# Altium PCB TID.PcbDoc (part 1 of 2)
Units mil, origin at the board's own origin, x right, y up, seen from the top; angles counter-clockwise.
Board outline 3536 x 3093.63 mil, 4 copper layers (Top Layer, Ground plane, Supply plane, Bottom Layer), stack 79.834 mil thick; 234 components, 122 nets, 591 pads, 178 vias.
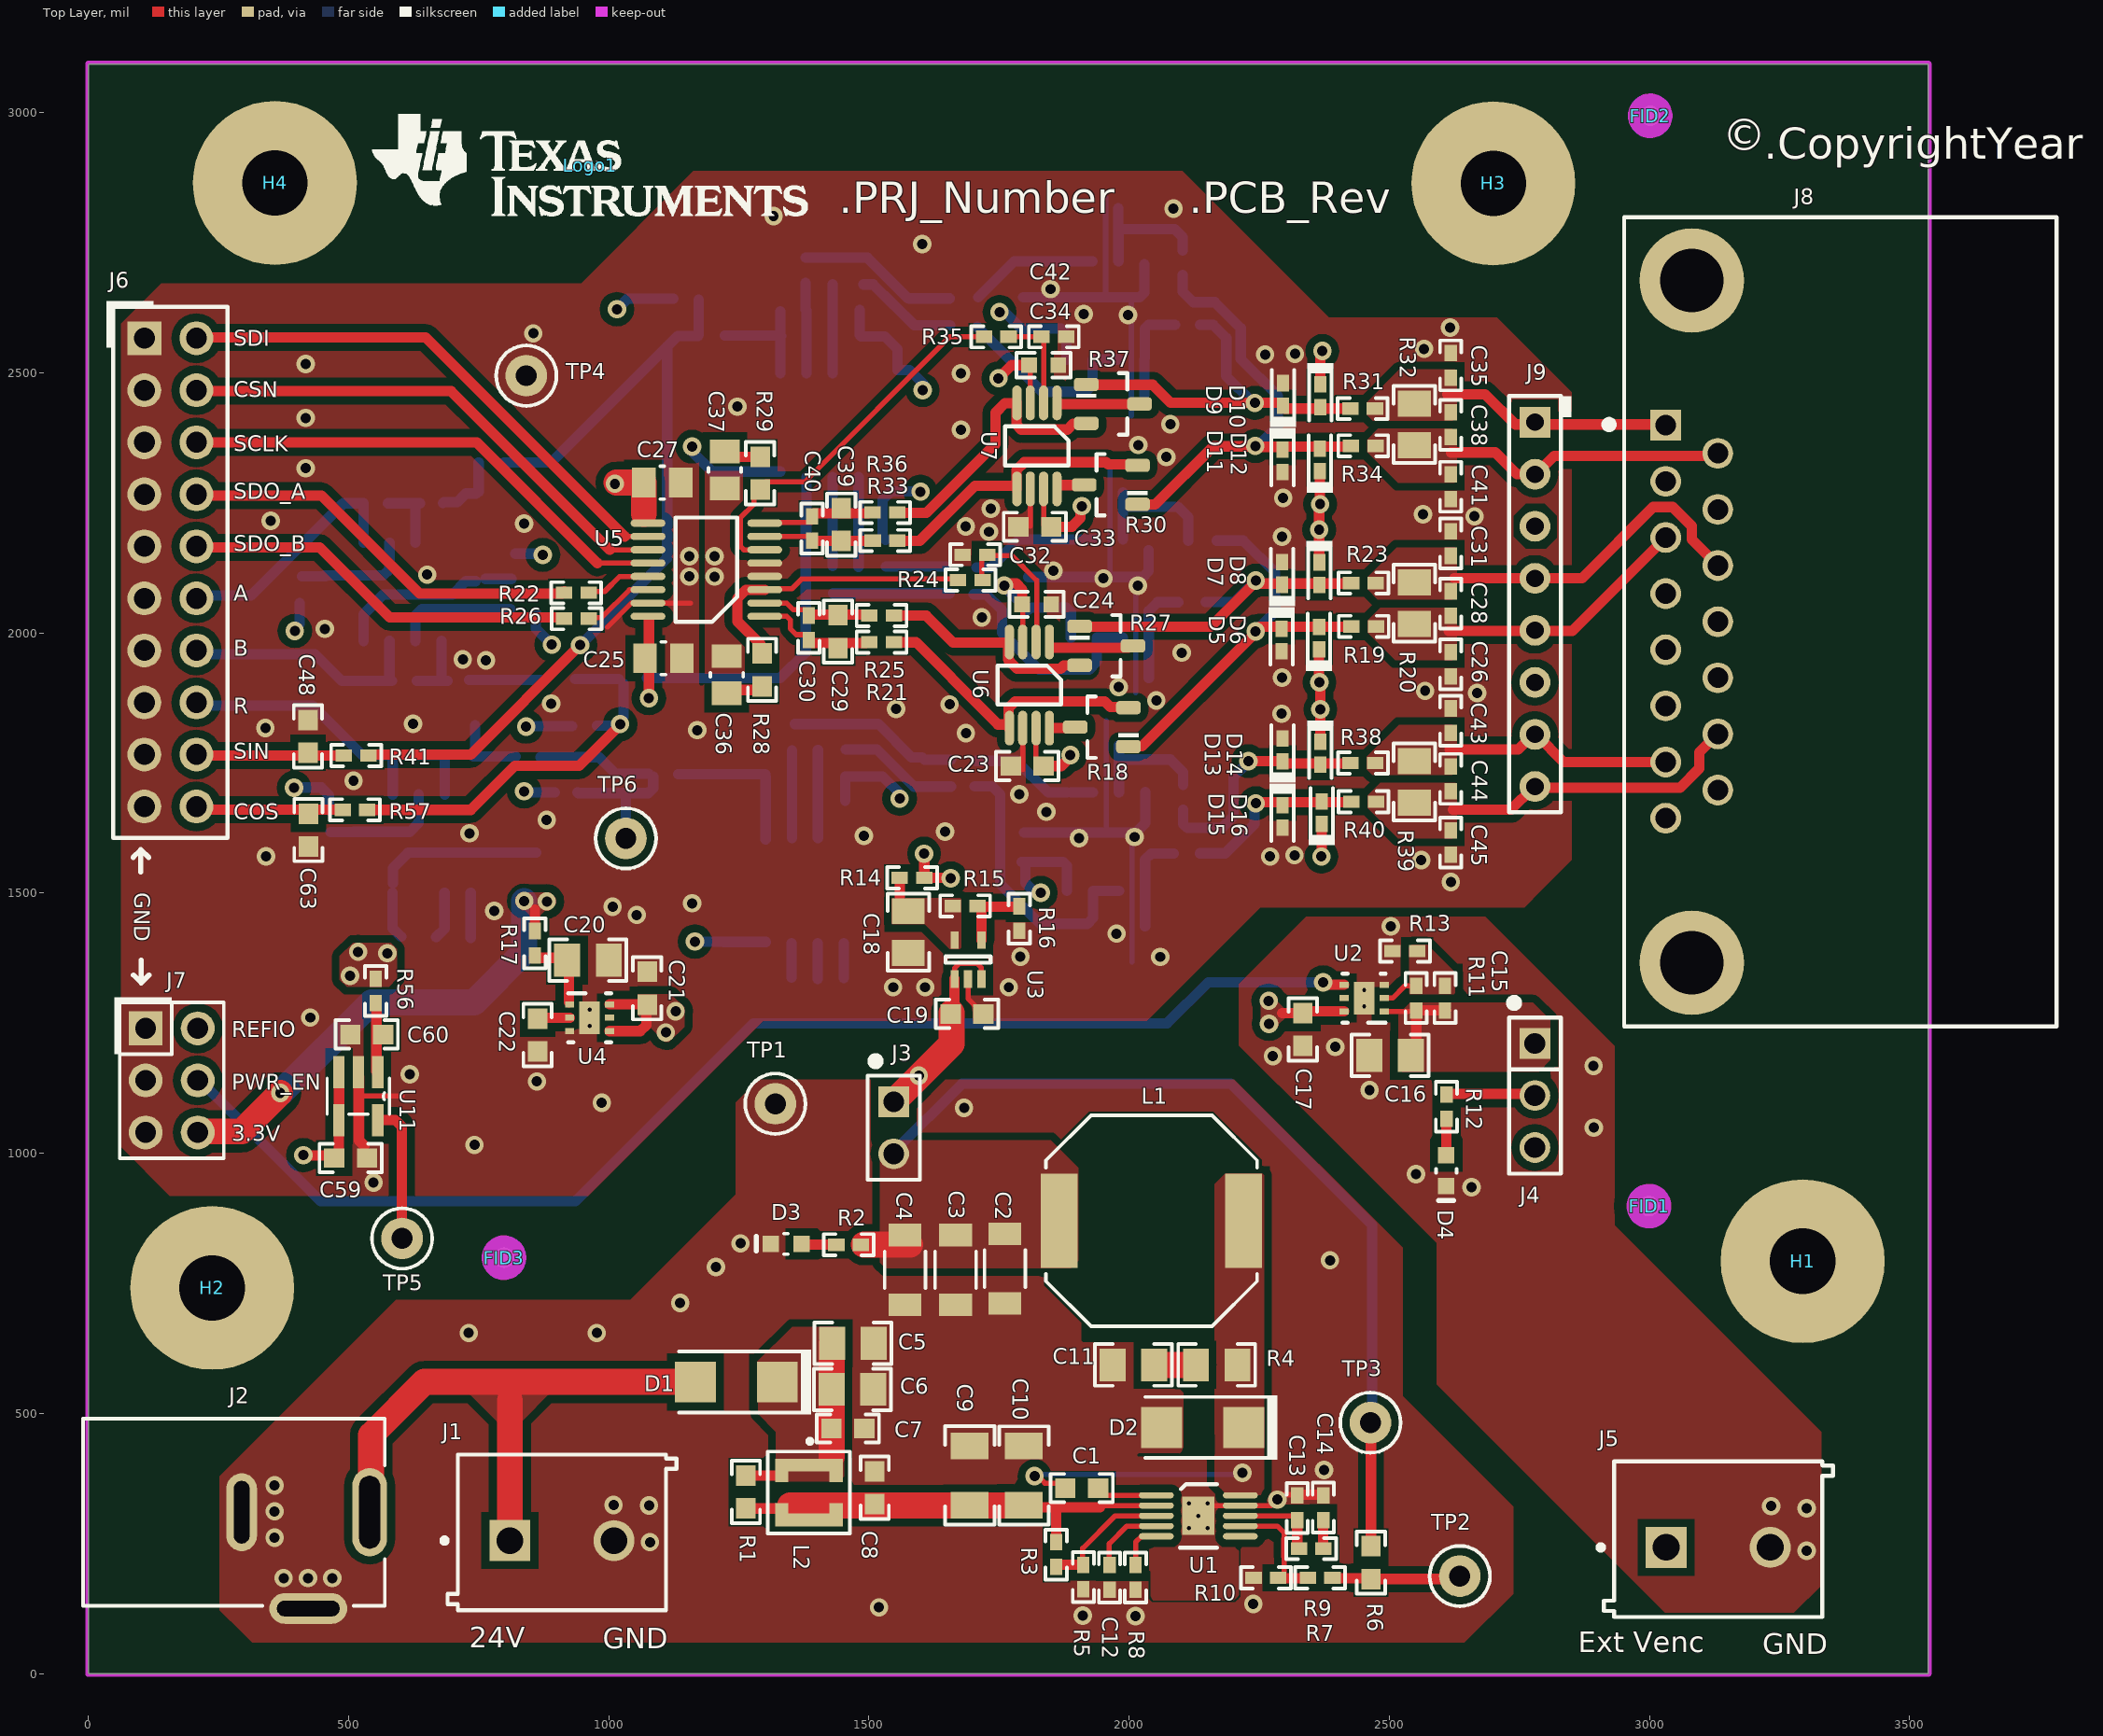
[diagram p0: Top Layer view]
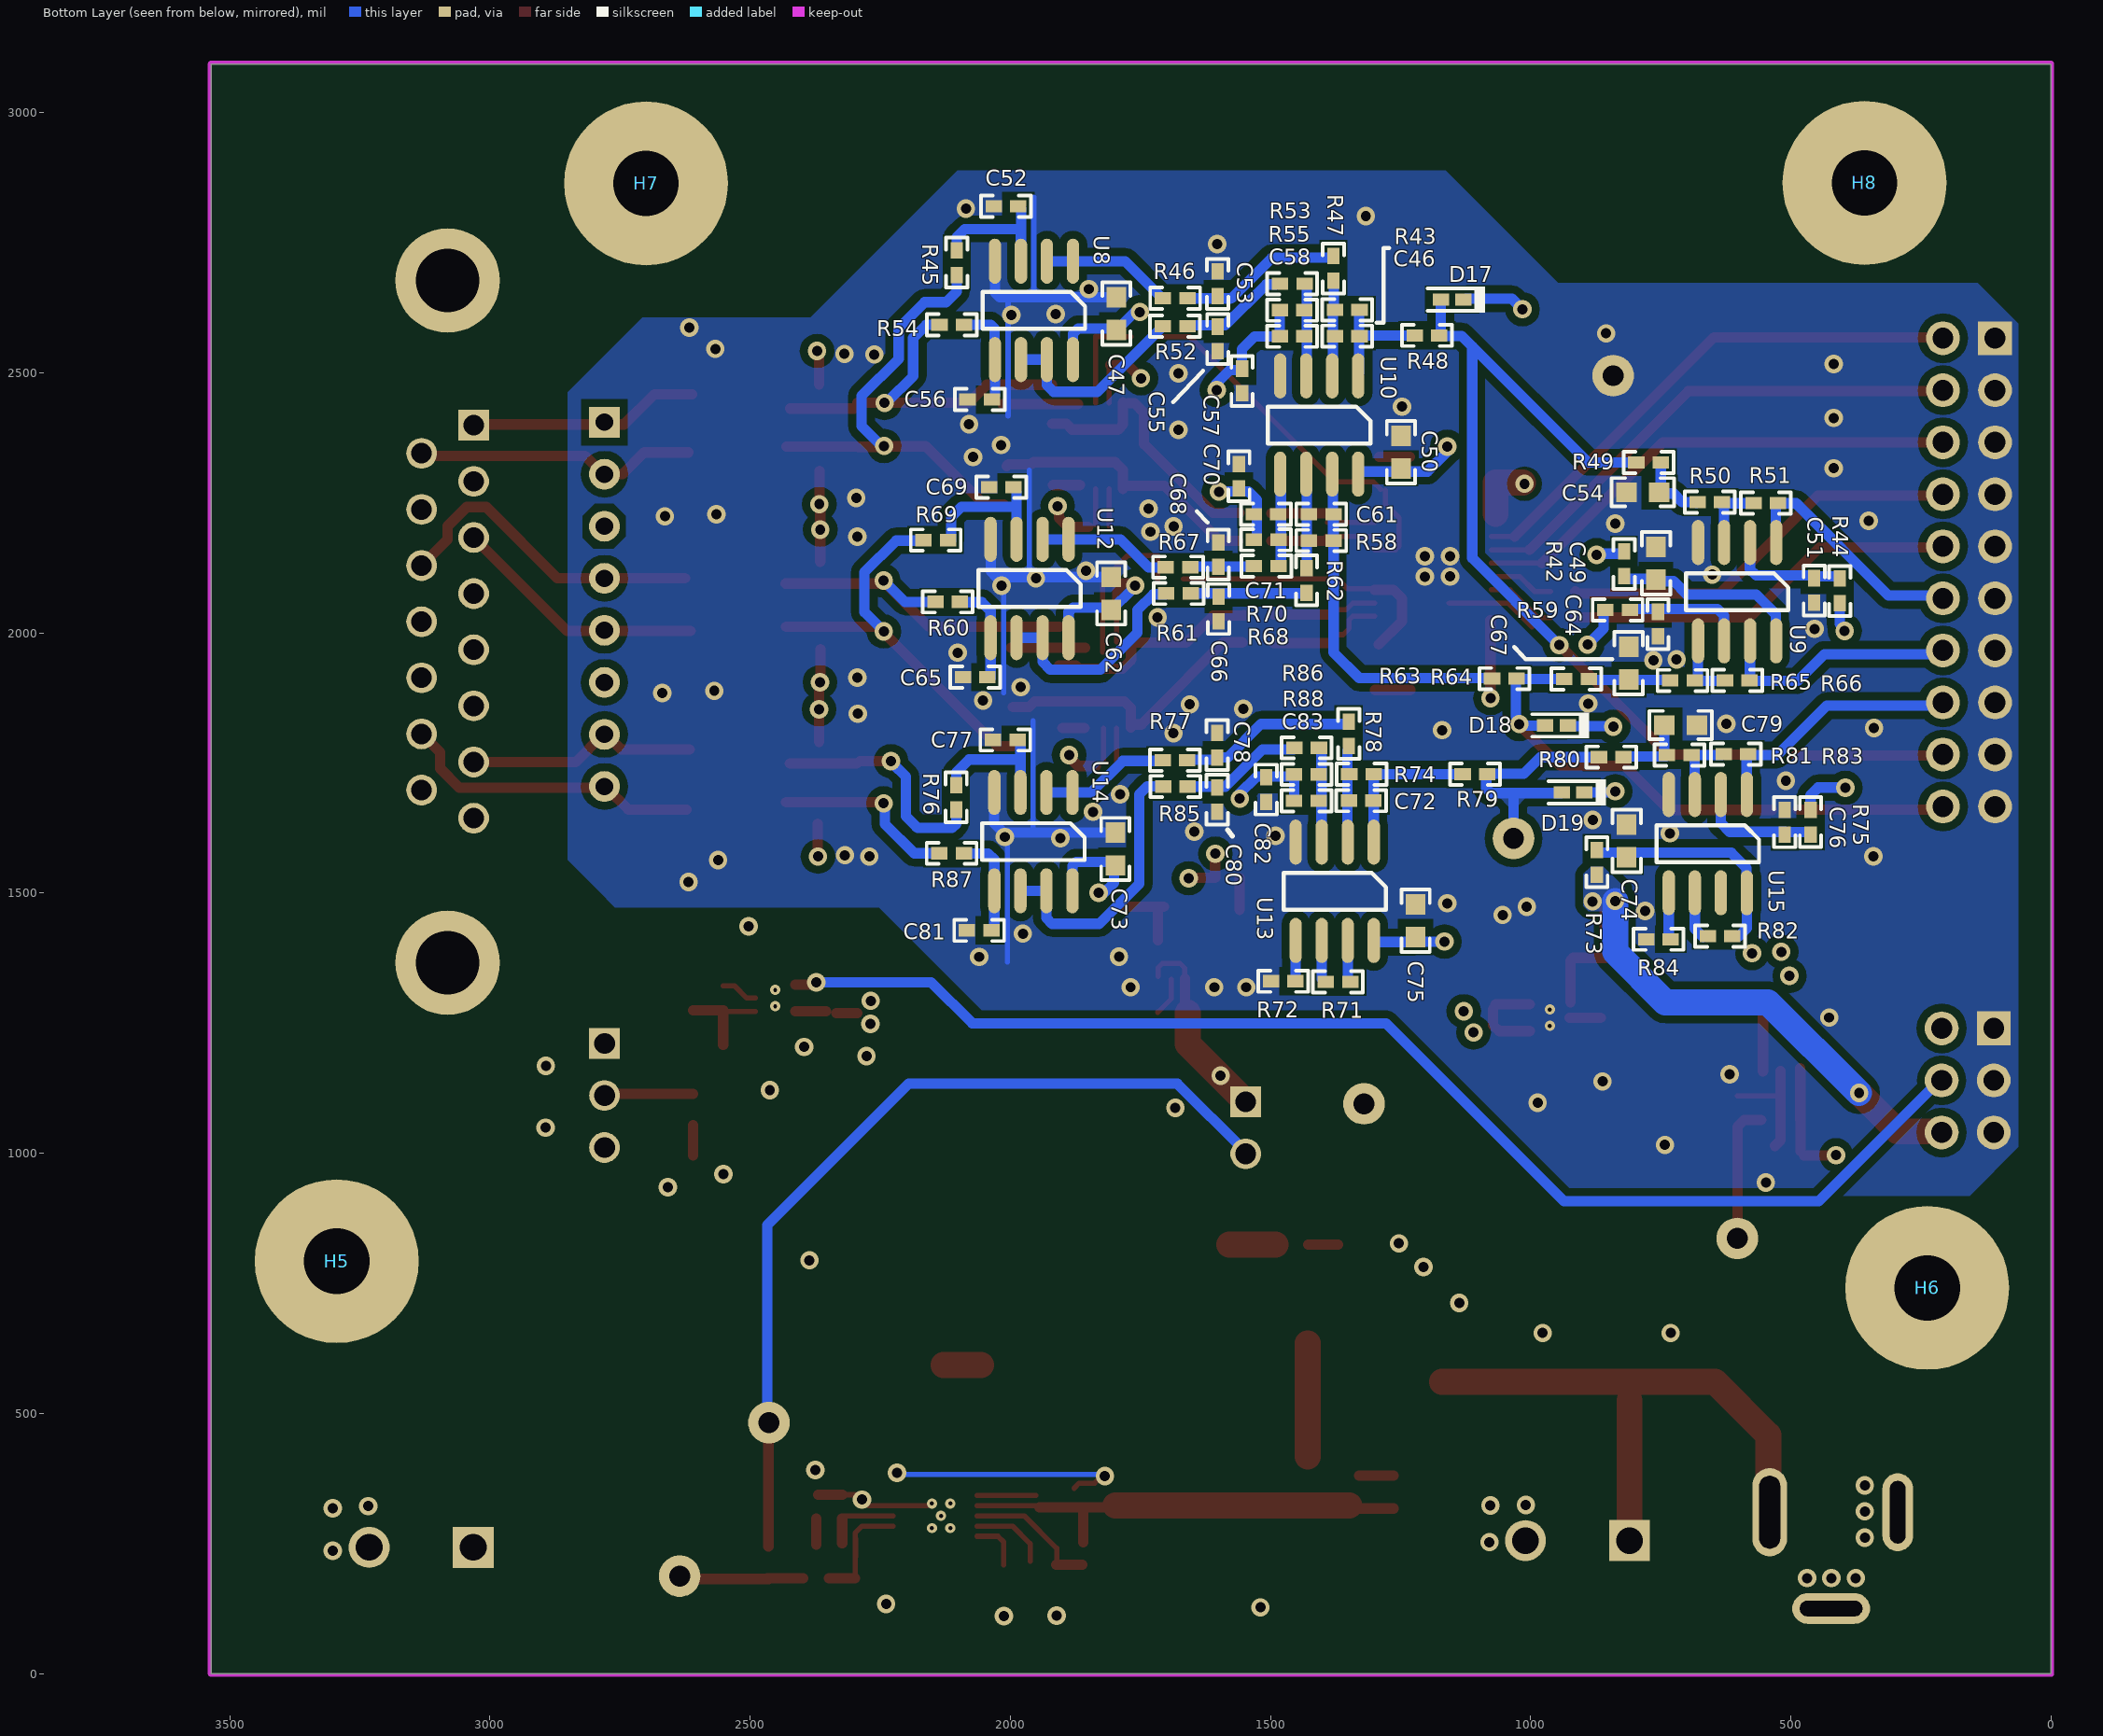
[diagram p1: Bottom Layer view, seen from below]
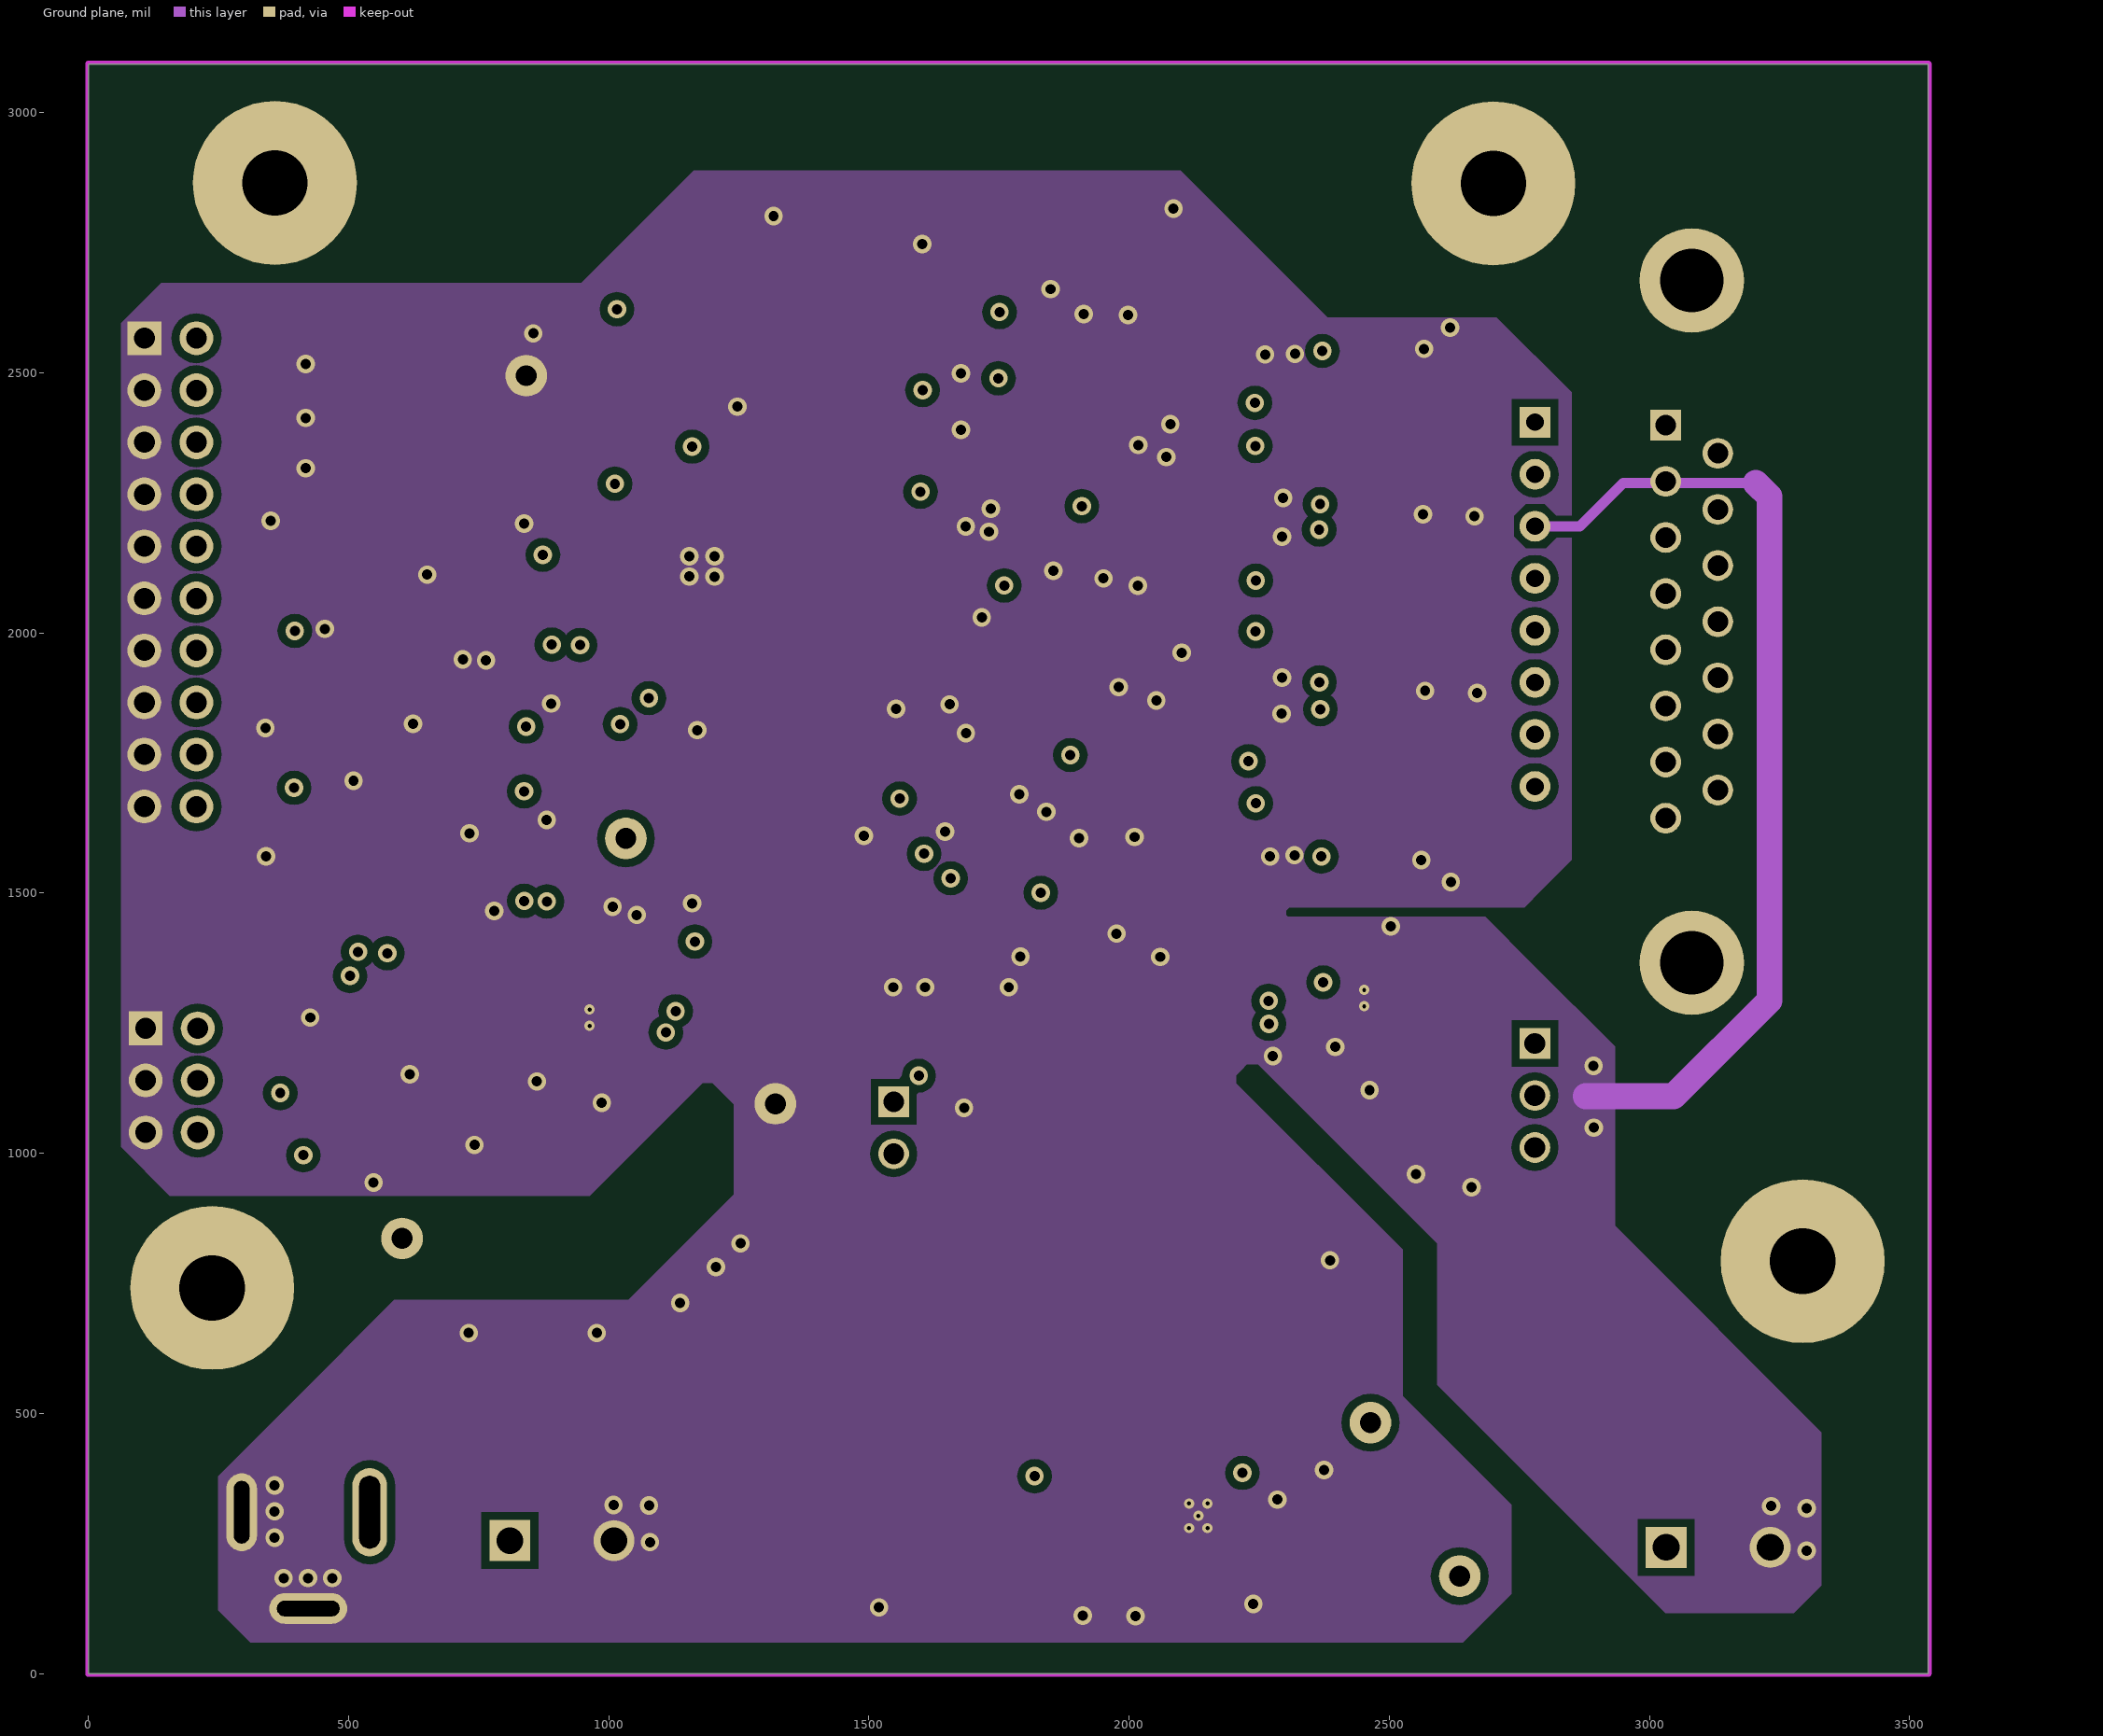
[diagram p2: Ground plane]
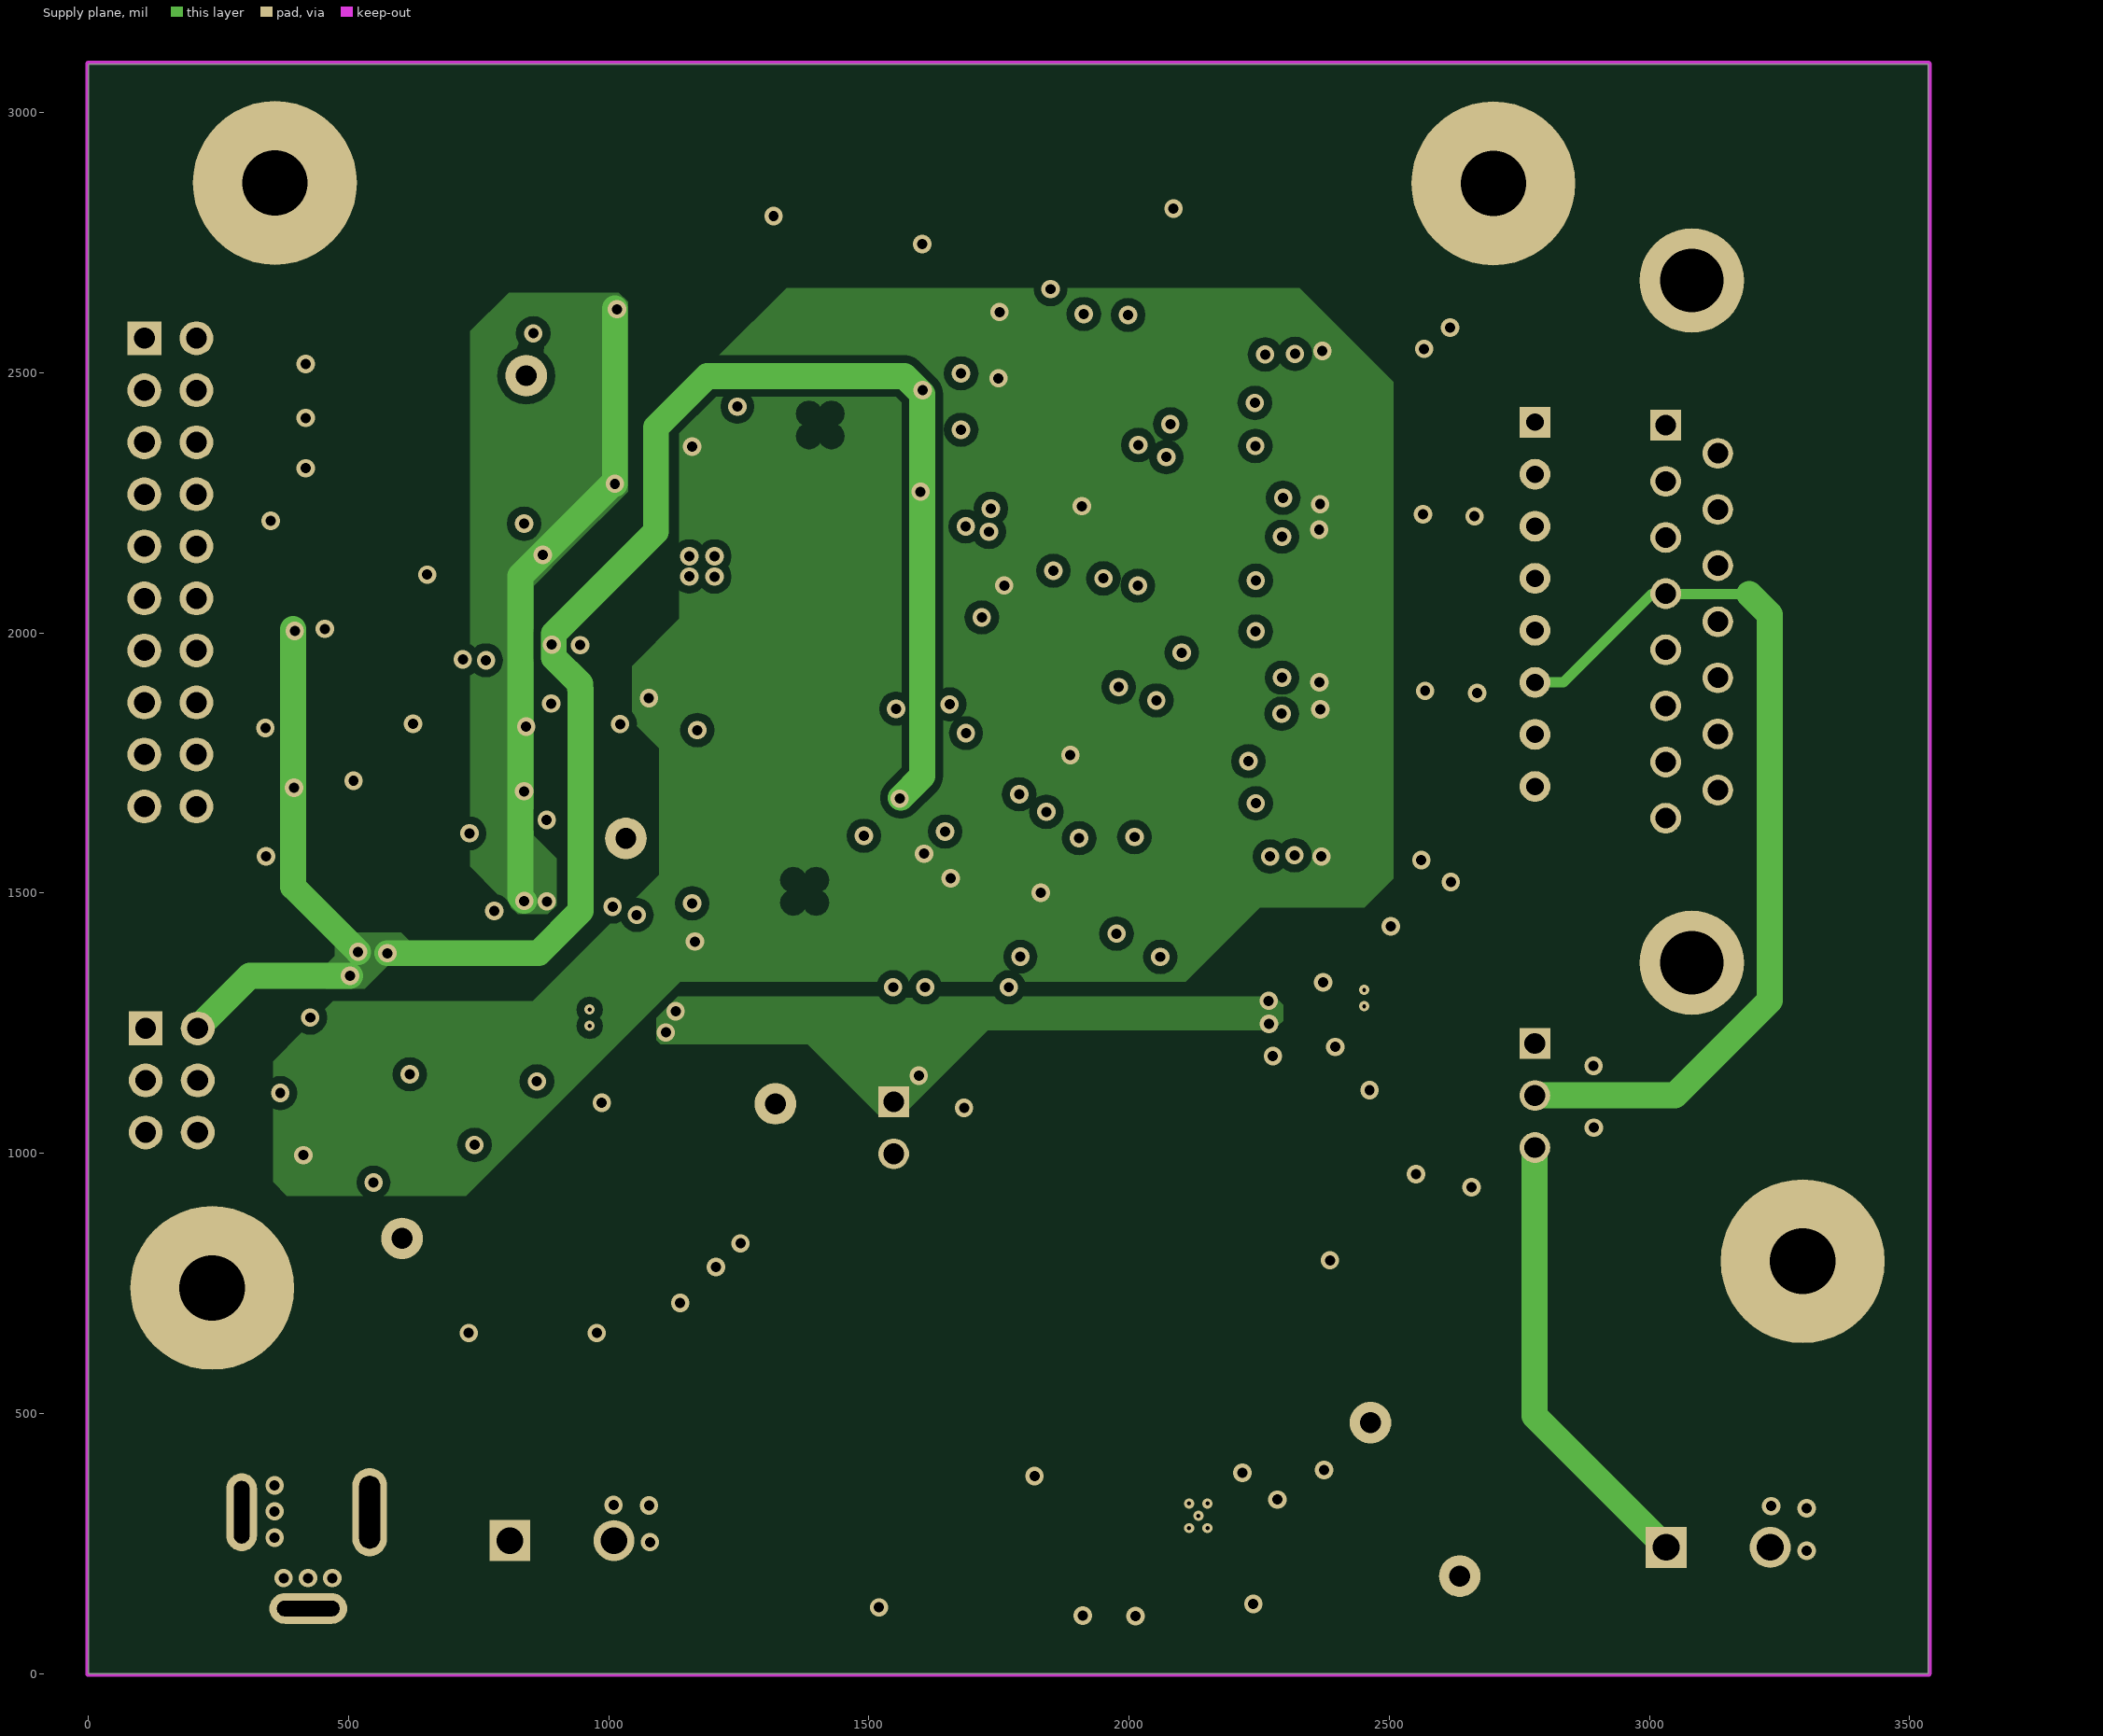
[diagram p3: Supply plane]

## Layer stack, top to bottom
Top Solder: solder mask 0.4, Solder Resist, Dk 3.5
Top Layer: signal copper 1.4
Dielectric1: core 59.2, FR-4, Dk 4.8
Ground plane: signal copper 1.417
Dielectric 3: prepreg 5, Dk 4.2
Supply plane: signal copper 1.417
Dielectric 2: core 10, Dk 4.2
Bottom Layer: signal copper 1.4
Bottom Solder: solder mask 0.4, Solder Resist, Dk 3.5

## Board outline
0,0 0,3093.63 3536,3093.63 3536,0

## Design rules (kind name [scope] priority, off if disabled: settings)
AcuteAngle [All] p1: minimum=4.50000000000000E+0001 checktracksonly=FALSE
AssemblyTestPointUsage [All] p1: valid=2
Clearance Clearance_Keepouts [((IsTrack Or IsArc) And Not InPoly) And IsFree and IsKeepOut vs ((IsTrack Or IsArc) And Not InPoly) And IsFree and IsKeepOut] p1: gap=0
Clearance Clearance_BoardEdge_MountingHoles [OnCopper and InComponentClass('Mounting Holes') vs IsKeepOut] p2: gap=40
Clearance Clearance_BoardEdge_Poly [OnCopper and InPoly vs IsKeepOut] p3: gap=25
Clearance Clearance_BoardEdge [OnCopper and Not InComponentClass('Logo') and not InComponentClass('FiducialMark') and not InRegion(1000,500,4000,800) and Not IsKeepout vs IsKeepOut] p4: gap=75
Clearance Clearance_Poly [InPolygon] p5: gap=15
Clearance [All] p6: gap=7.87
ComponentClearance ComponentClearance_MountingHoles_FiducialMarks [InComponentClass('Mounting Holes') vs InComponentClass('FiducialMark')] p1: gap=50 collisioncheckmode=3 verticalgap=10 showdistances=FALSE
ComponentClearance ComponentClearance_Shunt [InComponentClass('Header') vs InComponentClass('Shunt')] p2: gap=0 collisioncheckmode=3 verticalgap=0 showdistances=FALSE
ComponentClearance ComponentClearance_Logo [InComponentClass('Logo')] p3: gap=50 collisioncheckmode=3 verticalgap=10 showdistances=FALSE
ComponentClearance ComponentClearance_ScrewToNut [(HasFootprint('NY PMS 440 0025 PH')) vs (HasFootprint('Keystone_1902C'))] p4: gap=5 collisioncheckmode=3 verticalgap=10 showdistances=FALSE
ComponentClearance ComponentClearance_MountingHoles [InComponentClass('Mounting Holes')] p5: gap=118.11 collisioncheckmode=3 verticalgap=100000 showdistances=FALSE
ComponentClearance ComponentClearance_SmallPassives [HasFootprint('0201*') or HasFootprint('0402*') or HasFootprint('0508') or HasFootprint('0603*') or HasFootprint('0612') or HasFootprint('0805*') or HasFootprint('0815*') or HasFootprint('0830*') or HasFootprint('1206*') or HasFootprint('1210*') or HasFootprint('1808*') or HasFootprint('1812*') or HasFootprint('1825*') or HasFootprint('2010*') or HasFootprint('2220*') or HasFootprint('2225*') or HasFootprint('2512*') or HasFootprint('2728*') or HasFootprint('3518*') vs HasFootprint('0201*') or HasFootprint('0402*') or HasFootprint('0508') or HasFootprint('0603*') or HasFootprint('0612') or HasFootprint('0805*') or HasFootprint('0815*') or HasFootprint('0830*') or HasFootprint('1206*') or HasFootprint('1210*') or HasFootprint('1808*') or HasFootprint('1812*') or HasFootprint('1825*') or HasFootprint('2010*') or HasFootprint('2220*') or HasFootprint('2225*') or HasFootprint('2512*') or HasFootprint('2728*') or HasFootprint('3518*')] p6: gap=20 collisioncheckmode=3 verticalgap=10 showdistances=FALSE
ComponentClearance ComponentClearance_THtoSMT [IsThruComponent vs IsSMTComponent] p7: gap=100 collisioncheckmode=3 verticalgap=30 showdistances=FALSE
ComponentClearance ComponentClearance_THtoTH [IsThruComponent vs IsThruComponent] p8: gap=118.11 collisioncheckmode=3 verticalgap=30 showdistances=FALSE
ComponentClearance [All] p9: gap=40 collisioncheckmode=3 verticalgap=10 showdistances=FALSE
DiffPairsRouting [All] p1: maxlimit=100 minlimit=10 mostfreqgap=10 toplayer_minwidth=15 toplayer_maxwidth=15 toplayer_prefwidth=15 midlayer1_minwidth=15 midlayer1_maxwidth=15 midlayer1_prefwidth=15 midlayer2_minwidth=15 midlayer2_maxwidth=15 midlayer2_prefwidth=15 bottomlayer_minwidth=15 bottomlayer_maxwidth=15 bottomlayer_prefwidth=15 maxuncoupledlength=1000
FabricationTestPointUsage TestPointUsage [All] p1: valid=2 allowmultiple=FALSE
FabricationTestpoint Testpoint [All] p1: side=3 testpointundercomponent=TRUE minsize=40 maxsize=100 preferedsize=60 minholesize=0 maxholesize=40 preferedholesize=32 testpointgrid=1 allowsidetop=TRUE allowsidebottom=TRUE usegrid=TRUE gridtolerance=0.01
FanoutControl Fanout_LCC [IsLCC] p1: bgadir=Out bgaviamode=Centered fanoutstyle=Auto fanoutdirection=Alternating viagrid=1 // Fanout_LCC (Default Rule)
FanoutControl Fanout_BGA [IsBGA] p2: bgadir=Out bgaviamode=Centered fanoutstyle=Auto fanoutdirection=Alternating viagrid=1 // Fanout_BGA (Default Rule)
FanoutControl Fanout_Default [All] p4: bgadir=Out bgaviamode=Centered fanoutstyle=Auto fanoutdirection=Alternating viagrid=1 // Fanout_Default (Default Rule)
FanoutControl Fanout_Small [(CompPinCount < 5)] p5: bgadir=Out bgaviamode=Centered fanoutstyle=Auto fanoutdirection=OutThenIn viagrid=1 // Fanout_Small (Default Rule)
HoleSize HoleSize_componentPAD [((Component =U1)or (Component =U2)or (Component =U4)or (Component =U10)or (Component =U13)) and isVia] p1: absolutevalues=TRUE maxlimit=251 minlimit=7.87 maxpercent=80.000 minpercent=20.000
HoleSize [All] p2: absolutevalues=TRUE maxlimit=251 minlimit=8 maxpercent=80.000 minpercent=20.000
MinimumAnnularRing MinimumAnnularRing_ThermalPadVias [IsVia and InAnyComponent] p1: minimumring=5.91
MinimumAnnularRing [All] p2: minimumring=7.87
MinimumSolderMaskSliver MinimumSolderMaskSliver_Logo [InComponentClass('Logo') vs InComponentClass('Logo')] p1: minsoldermaskwidth=0.7
MinimumSolderMaskSliver [All] p2: minsoldermaskwidth=3.94
PlaneConnect [All] p1: planeconnectstyle=Direct reliefexpansion=10 reliefentries=4 reliefconductorwidth=10 reliefairgap=10
PolygonConnect PolygonConnect_1 [All vs IsNamedPolygon('Top Layer-5VDC-LDO')] p1: connectstyle=Direct reliefconductorwidth=10 reliefentries=4 polygonreliefangle="90 Angle" airgapwidth=10
PolygonConnect [All] p2: connectstyle=Direct reliefconductorwidth=10 reliefentries=4 polygonreliefangle="90 Angle" airgapwidth=10
RoutingVias ThermalPadVias [IsVia and InAnyComponent] p1: holewidth=7.87 width=19.68 viastyle="Through Hole" minholewidth=7.87 minwidth=19.68 maxholewidth=12.99 maxwidth=23.62
RoutingVias [All] p2: holewidth=16 width=34 viastyle="Through Hole" minholewidth=7.87 minwidth=26 maxholewidth=40 maxwidth=65
SilkToBoardRegionClearance [Not ((IsComment or IsDesignator) And (Hide <> 'False')) and not ( InRegion(1000,500,4000,800) or InRegion(665,1651,706,2036)or InRegion(4202,2766,4505,4364))] p1:
SilkToSilkClearance SilkToSilkClearance_Pb-FreeLogo [(HasFootprint('Pb-Free_Overlay_Medium') OR HasFootprint('Pb-Free_Overlay_Small')) vs (HasFootprint('Pb-Free_Overlay_Medium') OR HasFootprint('Pb-Free_Overlay_Small'))] p1: silktosilkclearance=0
SilkToSilkClearance [All] p2: silktosilkclearance=5
SilkToSolderMaskClearance "Silk to Solder Mask Opening" [not isVia vs not isVia] p1: minsilkscreentomaskgap=1 clearancetoexposedcopper=FALSE
SolderMaskExpansion [All] p1: expansion=1.97
UnpouredPolygon [All] p1: allowunpoured=FALSE
Width [All] p1: maxlimit=100 minlimit=6 preferedwidth=10 checkconnectedcopper=TRUE
14 further rules are at their usual default settings.

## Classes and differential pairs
component class TIDA-00176_SCLS: C23 C24 C25 C26 C27 C28 C29 C30 C31 C32 C33 C34 C35 C36 C37 C38 C39 C40 C41 C42 C43 C44 C45 D5 D6 D7 D8 D9 D10 D11 D12 D13 D14 D15 D16 J6 J7 J8 J9 R18 R19 R20 R21 R22 R23 R24 R25 R26 R27 R28 R29 R30 R31 R32 R33 R34 R35 R36 R37 R38 R39 R40 TP4 U5 U6 U7
component class TIDA-00176_SCHS: C46 C47 C48 C49 C50 C51 C52 C53 C54 C55 C56 C57 C58 C59 C60 C61 C62 C63 C64 C65 C66 C67 C68 C69 C70 C71 C72 C73 C74 C75 C76 C77 C78 C79 C80 C81 C82 C83 D17 D18 D19 R41 R42 R43 R44 R45 R46 R47 R48 R49 R50 R51 R52 R53 R54 R55 R56 R57 R58 R59 R60 R61 R62 R63 R64 R65 R66 R67 R68 R69 R70 R71 R72 R73 R74 R75 R76 R77 R78 R79 R80 R81 R82 R83 R84 R85 R86 R87 R88 R89 R90 R91 R92 R93 R95 R202 TP5 TP6 U8 U9 U10 U11 U12 U13 U14 U15
component class TIDA-00176_PS: C1 C2 C3 C4 C5 C6 C7 C8 C9 C10 C11 C12 C13 C14 C15 C16 C17 C18 C19 C20 C21 C22 D1 D2 D3 D4 J1 J2 J3 J4 J5 L1 L2 R1 R2 R3 R4 R5 R6 R7 R8 R9 R10 R11 R12 R13 R14 R15 R16 R17 TP1 TP2 TP3 U1 U2 U3 U4
component class Header: J3 J4 J6 J7 J9
component class FiducialMark: FID1 FID2 FID3
component class TIDA-00176_BD: FID1 FID2 FID3 H1 H2 H3 H4 H5 H6 H7 H8 Logo1
component class Logo: Logo1
component class "Mounting Holes": H1 H2 H3 H4

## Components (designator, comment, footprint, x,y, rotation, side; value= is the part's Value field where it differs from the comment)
C1 "GRM188R71H104KA93D" 0603 1908.78,356.53 r0 top
C2 "CGA5L3X5R1H106K160AB" 1206_190 1761.34,778.38 r270 top
C3 "CGA5L3X5R1H106K160AB" 1206_190 1666.49,776.08 r270 top
C4 "CGA5L3X5R1H106K160AB" 1206_190 1569.35,776.08 r270 top
C5 "GRM21BR71H105KA12L" 0805_HV 1469.44,634.86 r0 top
C6 "GRM216R71H103KA01D" 0805_HV 1468.44,546.4 r0 top
C7 "GRM188R71H104KA93D" 0603 1459.49,471.28 r0 top
C8 "GRM188R71H104KA93D" 0603 1511.11,357.5 r90 top
C9 "GRM31CR61H225KA88L" 1206 1693.74,380.97 r90 top
C10 "GRM31CR61H225KA88L" 1206 1797.82,380.84 r90 top
C11 "C2012X5R1H475K125AB" 0805_HV 2008.32,593.43 r180 top
C12 "GRM155R61C222KA01D" 0402 1962.46,185.05 r270 top
C13 "GRM1555C1H160JA01D" 0402 2323.07,318.69 r90 top
C14 "GRM155R71C472KA01D" 0402 2373.22,319.04 r90 top
C15 "GRM1555C1H160JA01D" 0402 2607.19,1298.32 r90 top
C16 "GRM219R61C106KA73D" 0805_HV 2501.65,1188.37 r180 top
C17 "GRM188R61C225KE15D" 0603 2333.77,1238.22 r270 top
C18 "GRM219R61C106KA73D" 0805_HV 1575.84,1425.38 r270 top
C19 "GRM188R61C225KE15D" 0603 1688.72,1267.92 r0 top
C20 "GRM219R61C106KA73D" 0805_HV 960.11,1371.37 r0 top
C21 "GRM188R61C225KE15D" 0603 1073.87,1317.42 r90 top
C22 "GRM188R71C103KA01D" 0603 863.32,1227.39 r270 top
C23 "GRM188R71C104KA01D" 0603 1804.13,1744.36 r0 top
C24 "GRM188R71C104KA01D" 0603_HV 1822.31,2055.28 r180 top
C25 "CL21B106KOQNNNE" 0805_140 1105.17,1951.51 r180 top
C26 "GRM1555C1H221JA01D" 0402 2618.06,1939.81 r90 top
C27 "CL21B106KOQNNNE" 0805_140 1102.97,2289.06 r180 top
C28 "GRM1555C1H221JA01D" 0402 2618.06,2056.63 r90 top
C29 "GRM1885C1H222JA01D" 0603 1440.49,2002.7 r90 top
C30 "GRM1555C1H102JA01D" 0402 1384.28,2009.99 r90 top
C31 "GRM1555C1H221JA01D" 0402 2618.06,2172.05 r90 top
C32 "GRM155R71C104KA88D" 0402 1703.95,2150.48 r180 top
C33 "GRM188R71C104KA01D" 0603 1818.89,2204.18 r0 top
C34 "GRM188R71C104KA01D" 0603_HV 1835.74,2514.85 r180 top
C35 "GRM1555C1H221JA01D" 0402 2618.06,2514.35 r270 top
C36 "GRM21BR71A106KE51K" 0805_140 1226.92,1919.92 r270 top
C37 "GRM21BR71A106KE51K" 0805_140 1223,2313.26 r270 top
C38 "GRM1555C1H221JA01D" 0402 2618.06,2400.28 r270 top
C39 "GRM1885C1H222JA01D" 0603 1446.8,2208.24 r90 top
C40 "GRM1555C1H102JA01D" 0402 1390.8,2200.87 r90 top
C41 "GRM1555C1H221JA01D" 0402 2618.06,2281.08 r270 top
C42 "GRM155R71C104KA88D" 0402 1855.39,2569.36 r0 top
C43 "GRM1555C1H221JA01D" 0402 2618.06,1831.5 r90 top
C44 "GRM1555C1H221JA01D" 0402 2618.06,1719.66 r90 top
C45 "GRM1555C1H221JA01D" 0402 2618.06,1597.34 r90 top
C46 "GRM1555C1H4R7WA01D" 0402 1352.54,2570.53 r0 bottom
C47 "GRM188R71C104KA01D" 0603 1796.17,2613.76 r270 bottom
C48 "GRM1885C1H222JA01D" 0603 422.05,1801.47 r90 top
C49 "GRM188R71C104KA01D" 0603 759.09,2133.9 r270 bottom
C50 "GRM188R71C104KA01D" 0603 1249.23,2347.67 r270 bottom
C51 "GRM155R71C104KA88D" 0402 455.1,2081.76 r270 bottom
C52 "GRM1555C1E470JA01D" 0402 2008.28,2820.37 r0 bottom
C53 "GRM1535C1H101JDD5D" 0402 1601.45,2671.05 r90 bottom
C54 "GRM1885C1H222JA01D" 0603 784.27,2270.49 r0 bottom
C55 "GRM1535C1H101JDD5D" 0402 1601.27,2565.16 r270 bottom
C56 "GRM1555C1E470JA01D" 0402 2058.57,2448.67 r0 bottom
C57 "GRM155R71C104KA88D" 0402 1554.57,2484.43 r270 bottom
C58 "GRM1555C1H4R7WA01D" 0402 1458.43,2570.25 r180 bottom
C59 "GRM188R71C104KA01D" 0603 504.14,991.03 r180 top
C60 "GRM188R71C104KA01D" 0603 534.86,1228.52 r0 top
C61 "GRM1555C1H4R7WA01D" 0402 1402.39,2228.3 r0 bottom
C62 "GRM188R71C104KA01D" 0603 1806.08,2076.12 r270 bottom
C63 "GRM1885C1H222JA01D" 0603 422.91,1621.34 r270 top
C64 "GRM155R71C104KA88D" 0402 755.36,2017.14 r270 bottom
C65 "GRM1555C1E470JA01D" 0402 2067.41,1915.19 r0 bottom
C66 "GRM1535C1H101JDD5D" 0402 1599.67,2046.1 r270 bottom
C67 "GRM1885C1H222JA01D" 0603 811.6,1942.32 r90 bottom
C68 "GRM1535C1H101JDD5D" 0402 1600.24,2150.7 r90 bottom
C69 "GRM1555C1E470JA01D" 0402 2017.27,2280.27 r0 bottom
C70 "GRM155R71C104KA88D" 0402 1560.67,2301.27 r90 bottom
C71 "GRM1555C1H4R7WA01D" 0402 1508.68,2228.22 r180 bottom
C72 "GRM1555C1H4R7WA01D" 0402 1325.67,1677.94 r0 bottom
C73 "GRM188R71C104KA01D" 0603 1798.1,1584.84 r270 bottom
C74 "GRM188R71C104KA01D" 0603 815.61,1600.31 r270 bottom
C75 "GRM188R71C104KA01D" 0603 1221.13,1447.15 r270 bottom
C76 "GRM155R71C104KA88D" 0402 511.74,1636.38 r90 bottom
C77 "GRM1555C1E470JA01D" 0402 2009.58,1794.56 r0 bottom
C78 "GRM1535C1H101JDD5D" 0402 1602.64,1784.43 r90 bottom
C79 "GRM1885C1H222JA01D" 0603 711.96,1822.86 r180 bottom
C80 "GRM1535C1H101JDD5D" 0402 1602.64,1679.72 r270 bottom
C81 "GRM1555C1E470JA01D" 0402 2059.86,1428.6 r0 bottom
C82 "GRM155R71C104KA88D" 0402 1508.12,1699.13 r270 bottom
C83 "GRM1555C1H4R7WA01D" 0402 1431,1677.58 r180 bottom
D1 "MBRA160T3G" SMA 1245.27,560.56 r180 top
D2 "MBRA160T3G" SMA 2141.3,473.35 r180 top
D3 "LG L29K-G2J1-24-Z" "LG L29K_GREEN" 1340.68,825.88 r180 top
D4 "LG L29K-G2J1-24-Z" "LG L29K_GREEN" 2609.49,966.58 r270 top
D5 "ZHCS350TA" SOD-523 2293.05,1986.56 r270 top
D6 "ZHCS350TA" SOD-523 2365.05,1990.2 r90 top
D7 "ZHCS350TA" SOD-523 2293.85,2114.46 r90 top
D8 "ZHCS350TA" SOD-523 2365.36,2114.15 r270 top
D9 "ZHCS350TA" SOD-523 2295.68,2458.62 r90 top
D10 "ZHCS350TA" SOD-523 2367.3,2456.03 r270 top
D11 "ZHCS350TA" SOD-523 2294.81,2330.83 r270 top
D12 "ZHCS350TA" SOD-523 2366.48,2332.94 r90 top
D13 "ZHCS350TA" SOD-523 2294.9,1775.38 r90 top
D14 "ZHCS350TA" SOD-523 2367.53,1769.1 r270 top
D15 "ZHCS350TA" SOD-523 2294.9,1647.75 r270 top
D16 "ZHCS350TA" SOD-523 2369.92,1654.92 r90 top
D17 "ZHCS350TA" SOD-523 1150.87,2640.75 r0 bottom
D18 "ZHCS350TA" SOD-523 950.33,1822.35 r0 bottom
D19 "ZHCS350TA" SOD-523 918.36,1693.87 r0 bottom
FID1 "Fiducial" Fiducial10-20 2998.98,898.59 r0 top
FID2 "Fiducial" Fiducial10-20 3001.29,2994.04 r0 top
FID3 "Fiducial" Fiducial10-20 798.71,799.49 r0 top
H1 "NY PMS 440 0025 PH" "NY PMS 440 0025 PH" 3294.31,792.71 r0 top locked
H2 "NY PMS 440 0025 PH" "NY PMS 440 0025 PH" 237.98,741.35 r0 top locked
H3 "NY PMS 440 0025 PH" "NY PMS 440 0025 PH" 2700.01,2864.16 r0 top locked
H4 "NY PMS 440 0025 PH" "NY PMS 440 0025 PH" 358.53,2865.08 r0 top locked
H5 "1902C" Keystone_1902C 3294.31,792.71 r180 bottom locked
H6 "1902C" Keystone_1902C 237.98,741.35 r180 bottom locked
H7 "1902C" Keystone_1902C 2700.01,2864.16 r180 bottom locked
H8 "1902C" Keystone_1902C 358.53,2865.08 r180 bottom locked
J1 "OSTTC022162" On-Shore_OSTTC022162 910.05,271.55 r0 top
J2 "RAPC722X" CONN_RAPC722X -0.37,310.34 r180 top
J3 "PEC02SAAN" CONN_PEC02SAAN 1547.62,1049.14 r270 top
J4 "PEC03SAAN" CONN_PEC03SAAN 2779.82,1111.17 r270 top
J5 "OSTTC022162" On-Shore_OSTTC022162 3132.01,258.51 r0 top
J6 "PEC10DAAN" SULLINS_PEC10DAAN 157.63,2116.57 r0 top
J7 "PEC03DAAN" SULLINS_PEC03DAAN 160.21,1140.24 r270 top
J8 "D-Sub-15_2rows_Female" "Harting_09 66 252 6610" 3541.87,2021.8 r0 top
J9 "800-10-008-10-001000" Mill-Max_800-10-008-10-001000 2779.94,2055.18 r270 top
L1 "744065101" WE-TPC-XLH2 2043.14,870.34 r180 top
L2 "LPS3010-102MLB" LPS3010 1384.57,348.2 r270 top
Logo1 "Texas Instruments" TI_Stacked_Overlay_Small 964.16,2899.03 r0 top
R1 "CRCW060310R0JNEAHP" 0603 1263.52,349.09 r270 top
R2 "CRCW04021K00JNED" 0402 1461.04,824.33 r0 top
R3 "CRCW0402681KFKED" 0402 1860.03,228.99 r90 top
R4 "CRCW080510K0JNEA" 0805_HV 2168.32,593.43 r0 top
R5 "CRCW040263K4FKED" 0402 1912.09,185.71 r90 top
R6 "CRCW060351R0JNEA" 0603 2464.7,213.43 r270 top
R7 "CRCW040264K9FKED" 0402 2367.12,184.26 r0 top
R8 "CRCW0402237KFKED" 0402 2012.15,185.05 r90 top
R9 "CRCW040246K4FKED" 0402 2349.9,240.31 r180 top
R10 "CRCW040210K0FKED" 0402 2262.79,184.24 r0 top
R11 "CRCW0402340KFKED" 0402 2551.65,1298.37 r270 top
R12 "CRCW04021K00JNED" 0402 2609.93,1089.69 r90 top
R13 "CRCW0402100KJNED" 0402 2529.96,1388.83 r0 top
R14 "CRCW04020000Z0ED" 0402 1582.91,1529.56 r0 top
R15 "CRCW0402845KFKED" 0402 1684.98,1475.42 r180 top
R16 "CRCW0402160KJNED" 0402 1789,1451.29 r90 top
R17 "CRCW04020000Z0ED" 0402 858.18,1403.72 r90 top
R18 "MPMT10015001AT1" SOT-23M 1947.5,1819.17 r180 top
R19 "CRCW040210R0FKED" 0402 2450.83,2012.6 r180 top
R20 "ESR10EZPF1200" 0805_HV 2548.25,2057.33 r270 top
R21 "CRCW040210R0FKED" 0402 1524.42,1982.49 r180 top
R22 "CRCW040222R0JNED" 0402 937.73,2077.3 r180 top
R23 "CRCW040210R0FKED" 0402 2450.23,2095.99 r180 top
R24 "CRCW040210R0JNED" 0402 1694.93,2101.92 r0 top
R25 "CRCW040210R0FKED" 0402 1524.42,2033.79 r180 top
R26 "CRCW040222R0JNED" 0402 938,2027.65 r180 top
R27 "MPMT10015001AT1" SOT-23M 1956.1,1975.38 r0 top
R28 "ERJ-3RQFR22V" 0603 1294.75,1929.19 r90 top
R29 "ERJ-3RQFR22V" 0603 1290.92,2307.23 r270 top
R30 "MPMT10015001AT1" SOT-23M 1964.94,2284.83 r180 top
R31 "CRCW040210R0FKED" 0402 2448.73,2431.36 r180 top
R32 "ESR10EZPF1200" 0805_HV 2548.25,2400.84 r90 top
R33 "CRCW040210R0FKED" 0402 1530.93,2177.62 r180 top
R34 "CRCW040210R0FKED" 0402 2449.93,2359.67 r180 top
R35 "CRCW040210R0JNED" 0402 1744.7,2569.36 r0 top
R36 "CRCW040210R0FKED" 0402 1530.8,2231.57 r180 top
R37 "MPMT10015001AT1" SOT-23M 1968.84,2440.23 r0 top
R38 "CRCW040210R0FKED" 0402 2449.21,1750.21 r180 top
R39 "ESR10EZPF1200" 0805_HV 2548.25,1713.98 r90 top
R40 "CRCW040210R0FKED" 0402 2450.66,1675.81 r180 top
R41 "CRCW0402100RJNED" 0402 514.62,1764.77 r180 top
R42 "CRCW04021R00JNED" 0402 820.54,2133.05 r90 bottom
R43 "ERA-2AEB8451X" 0402 1352.54,2621.09 r180 bottom
R44 "CRCW040210R0FKED" 0402 406.03,2080.9 r90 bottom
R45 "CRCW0402220RJNED" 0402 2102.65,2711.88 r90 bottom
R46 "CRCW0402332RFKED" 0402 1683.2,2643.47 r180 bottom
R47 "ERA-2AEB4751X" 0402 1379.05,2700.76 r270 bottom
R48 "CRCW040210R0FKED" 0402 1199.36,2571.96 r180 bottom
R49 "CRCW040220R0FKED" 0402 773.47,2327.86 r180 bottom
R50 "CRCW040226K7FKED" 0402 655.72,2251.33 r180 bottom
R51 "CRCW0402549KFKED" 0402 548.12,2249.7 r180 bottom
R52 "CRCW0402332RFKED" 0402 1683.34,2589.72 r180 bottom
R53 "ERA-2AEB4751X" 0402 1458.15,2671.17 r180 bottom
R54 "CRCW0402220RJNED" 0402 2112.45,2592.2 r180 bottom
R55 "ERA-2AEB8451X" 0402 1458.43,2620.49 r0 bottom
R56 "CRCW04020000Z0ED" 0402 552.33,1312.16 r90 top
R57 "CRCW0402100RJNED" 0402 512.33,1660.15 r180 top
R58 "ERA-2AEB8451X" 0402 1402.39,2177.61 r180 bottom
R59 "CRCW040210R0FKED" 0402 832.89,2044.23 r180 bottom
R60 "CRCW0402220RJNED" 0402 2120.32,2059.95 r180 bottom
R61 "CRCW0402332RFKED" 0402 1676.75,2076.11 r180 bottom
R62 "ERA-2AEB4751X" 0402 1430.64,2101.12 r90 bottom
R63 "CRCW040210R0FKED" 0402 1050.57,1912.29 r180 bottom
R64 "CRCW040220R0FKED" 0402 912.05,1911.44 r180 bottom
R65 "CRCW040226K7FKED" 0402 708.3,1908.69 r180 bottom
R66 "CRCW0402549KFKED" 0402 603.07,1908.94 r180 bottom
R67 "CRCW0402332RFKED" 0402 1677.68,2126.56 r180 bottom
R68 "ERA-2AEB4751X" 0402 1508.1,2128.49 r180 bottom
R69 "CRCW0402220RJNED" 0402 2143.16,2178.6 r180 bottom
R70 "ERA-2AEB8451X" 0402 1508.47,2179.3 r0 bottom
R71 "CRCW04021K00FKED" 0402 1370.3,1329.7 r0 bottom
R72 "CRCW04021K00FKED" 0402 1475.52,1330.83 r180 bottom
R73 "CRCW04021R00JNED" 0402 872.69,1559.34 r270 bottom
R74 "ERA-2AEB8451X" 0402 1324.96,1728.61 r180 bottom
R75 "CRCW040210R0FKED" 0402 462.14,1636.53 r270 bottom
R76 "CRCW0402220RJNED" 0402 2104.04,1684.16 r90 bottom
R77 "CRCW0402332RFKED" 0402 1683.64,1755.6 r180 bottom
R78 "ERA-2AEB4751X" 0402 1349.63,1806.21 r270 bottom
R79 "CRCW040210R0FKED" 0402 1107.04,1728.7 r180 bottom
R80 "CRCW040220R0FKED" 0402 845.17,1761.49 r180 bottom
R81 "CRCW040226K7FKED" 0402 714.36,1765.6 r180 bottom
R82 "CRCW04021K00FKED" 0402 636.02,1417.52 r0 bottom
R83 "CRCW0402549KFKED" 0402 605.57,1767.02 r180 bottom
R84 "CRCW04021K00FKED" 0402 754.42,1411.47 r180 bottom
R85 "CRCW0402332RFKED" 0402 1682.73,1705.06 r180 bottom
R86 "ERA-2AEB4751X" 0402 1430.57,1779.34 r180 bottom
R87 "CRCW0402220RJNED" 0402 2112.72,1576.66 r180 bottom
R88 "ERA-2AEB8451X" 0402 1431,1728.25 r0 bottom
TP1 "5001" Keystone5001 1320.23,1095.27 r0 top
TP2 "5000" Keystone5000 2635.38,187.61 r0 top
TP3 "5000" Keystone5000 2463.75,482.44 r0 top
TP4 "5001" Keystone5001 841.63,2494.58 r0 top
TP5 "5002" Keystone5002 602.91,836.51 r0 top
TP6 "5002" Keystone5002 1032.87,1605.27 r0 top
U1 "TPS54040ADGQ" DGQ0010D_N 2133.01,303.43 r0 top
U2 "TPS79901DRVR" DRV0006A 2451.65,1298.37 r180 top
U3 "TPS71701DCKR" DCK0005A_N 1690.49,1372.23 r90 top
U4 "TPS79933DRVR" DRV0006A 963.34,1260.64 r0 top
U5 "ADS8354IPWR" PW0016A_N 1187.64,2121.6 r180 top
U6 "THS4531AIDGK" DGK0008A_N 1808.36,1900.03 r270 top
U7 "THS4531AIDGK" DGK0008A_N 1822.9,2359.58 r270 top
U8 "OPA2365AIDR" D0008A_N 1954.56,2620.12 r270 bottom
U9 "TLV3202AID" D0008A_N 603.28,2079.38 r270 bottom
U10 "OPA2365AIDR" D0008A_N 1406.36,2399.77 r270 bottom
U11 "REF2033AIDDCR" DDC0005A_N 518.81,1109.76 r270 top
U12 "OPA2365AIDR" D0008A_N 1962.95,2085.55 r270 bottom
U13 "OPA2365AIDR" D0008A_N 1376.52,1503.6 r270 bottom
U14 "OPA2365AIDR" D0008A_N 1955.56,1599.08 r270 bottom
U15 "TLV3202AID" D0008A_N 659.59,1595.23 r270 bottom

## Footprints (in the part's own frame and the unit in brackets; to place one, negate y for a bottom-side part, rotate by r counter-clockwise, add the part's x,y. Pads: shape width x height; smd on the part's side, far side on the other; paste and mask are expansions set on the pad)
0402 [mm] "0402 from SM-752 data"
  rect 0.8x0.6 smd: 1(-0.6,0) 2(0.6,0)
  silkscreen extent -1.22,-0.52 1.22,0.52, body extent -0.55,-0.3 0.55,0.3, height 0.6
0603 [mm] "0603 from SM-752 data"
  rect 1x0.95 smd: 1(-0.8,0) 2(0.8,0)
  silkscreen extent -1.52,-0.69 1.52,0.69, body extent -0.87,-0.47 0.87,0.47, height 0.85
0603_HV [mil] "Ernesto recommended land pattern.  26 mil between pads."
  rect 30x30 smd: 1(-28,0) 2(28,0)
  silkscreen extent -52,-24 52,24, body extent -34,-19 34,19, height 33
0805_140 [mm] "0805 / 1.4mm height"
  rect 1.15x1.45 smd: 1(-0.9,0) 2(0.9,0)
  silkscreen extent -0.1,-0.8 0.1,0.8, body extent -1.1,-0.72 1.1,0.72, height 1.4
0805_HV [mil] "0805 with 30mil clearance between pads"
  rect 50x63 smd: 1(-40,0) 2(40,0)
  silkscreen extent -74,-40 74,40, body extent -43,-29 43,29, height 43
1206 [mm] "1206 from SM-752 data"
  rect 1.3x1.85 smd: 1(-1.45,0) 2(1.45,0)
  silkscreen extent -2.4,-1.21 2.4,1.21, body extent -1.7,-0.9 1.7,0.9, height 1.35
1206_190 [mm] "1206_190"
  rect 1.1x1.6 smd: 1(-1.7,0) 2(1.7,0)
  silkscreen extent -0.9,-1 0.9,1, body extent -1.75,-0.95 1.75,0.95, height 1.9
CONN_PEC02SAAN [mm] "SULLINS"
  rect 1.5x1.5 hole 1.016: 1(-1.27,0)
  round 1.5 hole 1.016: 2(1.27,0)
  silkscreen extent -3.45,-1.27 2.54,1.27, body extent -2.54,-1.27 2.54,1.27, height 8.38
CONN_PEC03SAAN [mm] "SULLINS"
  rect 1.5x1.5 hole 1.016: 1(-2.54,0)
  round 1.5 hole 1.016: 2(0,0) 3(2.54,0)
  silkscreen extent -4.72,-1.27 3.81,1.27, body extent -3.84,-1.3 3.84,1.3, height 8.38
CONN_RAPC722X [mm] "Conn_DC Jack"
  oval 1.7x4.3 hole 1.01 slot 3.56 at 90 deg: 1(-13.741,0)
  oval 1.5x3.8 hole 0.76 slot 3.05 at 90 deg: 2(-7.493,0)
  oval 3.8x1.5 hole 0.76 slot 3.05 at 0 deg: 3(-10.744,4.7)
  silkscreen extent -14.48,-4.57 0.25,4.57, body extent -14.5,-4.57 0.23,4.83, height 11.18
D0008A_N [mm] "SOIC, 8-Leads, Body 4.9x3.9mm, Pitch 1.27mm, IPC Medium Density"
  oval 2.2x0.6 smd: 1(-2.4,1.905) 2(-2.4,0.635) 3(-2.4,-0.635) 4(-2.4,-1.905) 5(2.4,-1.905) 6(2.4,-0.635) 7(2.4,0.635) 8(2.4,1.905)
  silkscreen extent -0.9,-2.5 0.9,2.5, body extent -3,-2.45 3,2.45, height 1.63
DCK0005A_N [mm] "SOT353, 5-Leads, Body 2x1.3mm, Pitch 0.65mm, Lead Span 2.1mm, IPC Medium Density"
  rect 0.85x0.4 smd: 1(-0.95,0.65) 2(-0.95,0) 3(-0.95,-0.65) 4(0.95,-0.65) 5(0.95,0.65)
  silkscreen extent -0.15,-1.1 0.15,1.1, body extent -1.14,-1 1.14,1, height 0.94
DDC0005A_N [mil]
  rect 62x22 smd: 1(-46,37.4) 2(-46,0) 3(-46,-37.4) 4(46,-37.4) 5(46,37.4)
  silkscreen extent -35,-60 35,60, body extent -60,-60 60,60, height 43
DGK0008A_N [mm] "TSOP, 8-Leads, Body 3x3mm, Pitch 0.65mm, IPC Medium Density"
  oval 1.7x0.45 smd mask+0.05: 1(-2.1,0.975) 2(-2.1,0.325) 3(-2.1,-0.325) 4(-2.1,-0.975) 5(2.1,-0.975) 6(2.1,-0.325) 7(2.1,0.325) 8(2.1,0.975)
  silkscreen extent -0.95,-1.55 0.95,1.55, body extent -2.45,-1.5 2.45,1.5, height 0.94
DGQ0010D_N [mm] "TSSOP, 10-Leads, Body 3x3mm, Pitch 0.5mm, Thermal Pad 1.88x1.57mm, IPC Medium Density"
  oval 1.7x0.3 smd: 1(-2.05,1) 2(-2.05,0.5) 3(-2.05,0) 4(-2.05,-0.5) 5(-2.05,-1) 6(2.05,-1) 7(2.05,-0.5) 8(2.05,0) 9(2.05,0.5) 10(2.05,1)
  rect 1.57x1.88 smd: 11(0,0)
  silkscreen extent -0.9,-1.55 0.9,1.55, body extent -2.45,-1.5 2.45,1.5, height 0.94
DRV0006A [mm] "SON, 6-Leads, Body 2x2mm, Pitch 0.65mm, Thermal Pad 1.6x1mm, TI Recommended"
  rect 0.45x0.3 smd: 1(-0.975,0.65) 2(-0.975,0) 3(-0.975,-0.65) 4(0.975,-0.65) 5(0.975,0) 6(0.975,0.65)
  rect 1x1.6 smd paste-0.5: 7(0,0)
  silkscreen extent -1.05,-1.2 1.05,1.2, body extent -1.05,-1.05 1.05,1.05, height 0.81
Fiducial10-20 [mm]
  round 1 smd mask+0.5: 1(0,0)
  Top Layer keep-out circle w1.178: c0,0 r0.5
"Harting_09 66 252 6610" [mm] "Harting"
  rect 1.5x1.5 hole 1 paste+0: 1(-12.97,9.59)
  round 1.5 hole 1 paste+0: 2(-12.97,6.85) 3(-12.97,4.11) 4(-12.97,1.37) 5(-12.97,-1.37) 6(-12.97,-4.11) 7(-12.97,-6.85) 8(-12.97,-9.59) 9(-10.43,8.22) 10(-10.43,5.48) 11(-10.43,2.74) 12(-10.43,0) 13(-10.43,-2.74) 14(-10.43,-5.48) 15(-10.43,-8.22)
  round 5.1 hole 3.1 paste+0: 16(-11.7,-16.65) 17(-11.7,16.65)
  silkscreen extent -15.86,-19.75 6.1,19.75, body extent -15,-19.75 6.1,19.75, height 13.6
Keystone5000 [mil] "For Keystone 500x miniature loop terminals"
  round 80 hole 40: 1(0,0)
  silkscreen extent -58,-58 58,58, body extent -49,-49 49,49, height 182
Keystone5001 [mil] "For Keystone 500x miniature loop terminals"
  round 80 hole 40: 1(0,0)
  silkscreen extent -58,-58 58,58, body extent -49,-49 49,49, height 182
Keystone5002 [mil] "For Keystone 500x miniature loop terminals"
  round 80 hole 40: 1(0,0)
  silkscreen extent -58,-58 58,58, body extent -49,-49 49,49, height 182
Keystone_1902C [mil] "Hex Standoff, 4-40 threaded, nylon"
  body extent -145,-126 146,126, height 501
"LG L29K_GREEN" [mm] "OSRAM"
  rect 0.8x0.8 smd paste-0.4: 1(-0.75,0) 2(0.75,0)
  silkscreen extent -0.1,-0.5 1.45,0.5, body extent -0.9,-0.45 0.9,0.45, height 0.67
LPS3010 [mm] "Coilcraft recommended land pattern.  Document 428-2, rev 10/6/08"
  rect 0.63x3.3 smd: 1(-1.335,0) 2(1.335,0)
  rect 1.14x0.64 smd: 1(-1.08,1.33) 1(-1.08,-1.33) 2(1.08,1.33) 2(1.08,-1.33)
  silkscreen extent -2.59,-2 2,2, body extent -1.58,-1.58 1.58,1.58, height 1.02
Mill-Max_800-10-008-10-001000 [mm] "Mill-Max"
  rect 1.5x1.5 hole 0.85: 1(-8.89,0)
  round 1.5 hole 0.85: 2(-6.35,0) 3(-3.81,0) 4(-1.27,0) 5(1.27,0) 6(3.81,0) 7(6.35,0) 8(8.89,0)
  silkscreen extent -10.16,-1.27 10.16,1.78, body extent -10.16,-1.27 10.16,1.27, height 8.13
"NY PMS 440 0025 PH" [mm] "4-40 nylon screw and mounting hole"
  round 8 hole 3.2: 1(0,0)
  body extent -3.3,-3.3 3.3,3.3, height 2.69
On-Shore_OSTTC022162 [mm] "THD, 2-Leads, Body 10.16x7.6mm, Pitch 5.08mm"
  rect 2x2 hole 1.3: 1(-2.54,-0.4)
  round 2 hole 1.3: 2(2.54,-0.4)
  silkscreen extent -5.85,-3.8 5.6,3.8, body extent -5.58,-3.8 5.6,3.8, height 10.31
PW0016A_N [mm] "TSOP, 16-Leads, Body 5x4.4mm, Pitch 0.65mm, IPC Medium Density"
  oval 1.7x0.35 smd: 1(-2.85,2.275) 2(-2.85,1.625) 3(-2.85,0.975) 4(-2.85,0.325) 5(-2.85,-0.325) 6(-2.85,-0.975) 7(-2.85,-1.625) 8(-2.85,-2.275) 9(2.85,-2.275) 10(2.85,-1.625) 11(2.85,-0.975) 12(2.85,-0.325) 13(2.85,0.325) 14(2.85,0.975) 15(2.85,1.625) 16(2.85,2.275)
  silkscreen extent -1.5,-2.55 1.5,2.55, body extent -3.21,-2.5 3.21,2.5, height 0.98
SMA [mm] "Molded Diode, 2-Leads, Body 4.3x2.6mm, IPC Medium Density, based on OnSemi component dimensions and land pattern"
  rect 2x2 smd: 1(-2,0) 2(2,0)
  silkscreen extent -3.66,-1.57 2.79,1.57, body extent -2.6,-1.3 2.6,1.3, height 2.42
SOD-523 [mm] "NXP Semiconductor recommended land pattern, nominal STEP model"
  rect 0.8x0.6 smd paste-0.05: 1(-0.55,0) 2(0.55,0)
  silkscreen extent -1.6,-0.63 1.2,0.64, body extent -0.8,-0.4 0.8,0.4, height 0.72
SOT-23M [mm] "SOT23, 3-Leads, Body 2.9x1.3mm, Pitch 0.95mm, Lead Span 2.5mm, IPC Low Density"
  rrect50% 1.2x0.65 smd: 1(-1.3,0.95) 2(-1.3,-0.95) 3(1.3,0)
  silkscreen extent -1.8,-1.5 0.7,1.5, body extent -1.16,-1.45 1.21,1.45, height 1
SULLINS_PEC03DAAN [mm] "SULLINS"
  rect 1.65x1.65 hole 1.016 mask+0: 1(-2.54,-1.27)
  round 1.65 hole 1.016 mask+0: 2(-2.54,1.27) 3(0,-1.27) 4(0,1.27) 5(2.54,-1.27) 6(2.54,1.27)
  silkscreen extent -4.06,-2.79 3.81,2.54, body extent -3.81,-2.54 3.81,2.54, height 8.38
SULLINS_PEC10DAAN [mm] "SULLINS"
  rect 1.65x1.65 hole 1.016: 1(-1.27,11.43)
  round 1.65 hole 1.016: 2(1.27,11.43) 3(-1.27,8.89) 4(1.27,8.89) 5(-1.27,6.35) 6(1.27,6.35) 7(-1.27,3.81) 8(1.27,3.81) 9(-1.27,1.27) 10(1.27,1.27) 11(-1.27,-1.27) 12(1.27,-1.27) 13(-1.27,-3.81) 14(1.27,-3.81) 15(-1.27,-6.35) 16(1.27,-6.35) 17(-1.27,-8.89) 18(1.27,-8.89) 19(-1.27,-11.43) 20(1.27,-11.43)
  silkscreen extent -3.11,-12.96 2.79,13.25, body extent -2.79,-12.96 2.79,12.96, height 9.08
TI_Stacked_Overlay_Small [mil]
  silkscreen extent -418,-98 418,98
WE-TPC-XLH2 [mm] "Wurth Elektronik recommended land pattern, 2008-04-11"
  rect 1.8x4.6 smd: 1(-4.5,0) 2(4.5,0)
  silkscreen extent -5.15,-5.15 5.15,5.15, body extent -5.15,-5.15 5.15,5.15, height 3.1

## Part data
C1 C7 C8: "CAP, CERM, 0.1 µF, 50 V, +/- 10%, X7R, 0603"
C2 C3 C4: "CAP, CERM, 10 µF, 50 V, +/- 10%, X5R, 1206_190"
C5: "CAP, CERM, 1 µF, 50 V, +/- 10%, X7R, 0805"
C6: "CAP, CERM, 0.01 µF, 50 V, +/- 10%, X7R, 0805"
C9 C10: "CAP, CERM, 2.2uF, 50V, +/-10%, X5R, 1206"
C11: "CAP, CERM, 4.7 µF, 50 V, +/- 10%, X5R, 0805"
C12: "CAP, CERM, 2200 pF, 16 V, +/- 10%, X5R, 0402"
C13 C15: "CAP, CERM, 16 pF, 50 V, +/- 5%, C0G/NP0, 0402"
C14: "CAP, CERM, 4700 pF, 16 V, +/- 10%, X7R, 0402"
C16 C18 C20: "CAP, CERM, 10 µF, 16 V, +/- 10%, X5R, 0805"
C17 C19 C21: "CAP, CERM, 2.2 µF, 16 V, +/- 10%, X5R, 0603"
C22: "CAP, CERM, 0.01 µF, 16 V, +/- 10%, X7R, 0603"
C23 C24 C33 C34 C47 C49 C50 C59 C60 C62 C73 C74 C75: "CAP, CERM, 0.1 µF, 16 V, +/- 10%, X7R, 0603"
C25 C27: "CAP, CERM, 10 µF, 16 V, +/- 10%, X7R, 0805_140"
C26 C28 C31 C35 C38 C41 C43 C44 C45: "CAP, CERM, 220 pF, 50 V, +/- 5%, C0G/NP0, 0402"
C29 C39 C48 C54 C63 C67 C79: "CAP, CERM, 2200 pF, 50 V, +/- 5%, C0G/NP0, 0603"
C30 C40: "CAP, CERM, 1000 pF, 50 V, +/- 5%, C0G/NP0, 0402"
C32 C42 C51 C57 C64 C70 C76 C82: "CAP, CERM, 0.1 µF, 16 V, +/- 10%, X7R, 0402"
C36 C37: "CAP, CERM, 10 µF, 10 V, +/- 10%, X7R, 0805_140"
C46 C58 C61 C71 C72 C83: "CAP, CERM, 4.7 pF, 50 V, +/- 1%, C0G/NP0, 0402"
C52 C56 C65 C69 C77 C81: "CAP, CERM, 47 pF, 25 V, +/- 5%, C0G/NP0, 0402"
C53 C55 C66 C68 C78 C80: "CAP, CERM, 100 pF, 50 V, +/- 5%, C0G/NP0, 0402"
D1 D2: "Diode, Schottky, 60V, 1A, SMA"
D3 D4: "LED, Green, SMD"
D5 D6 D7 D8 D9 D10 D11 D12 D13 D14 D15 D16 D17 D18 D19: "Diode, Schottky, 40 V, 0.35 A, SOD-523"
FID1 FID2 FID3: "Fiducial mark.  There is nothing to buy or mount."
H1 H2 H3 H4: "Machine Screw, Round, #4-40 x 1/4, Nylon, Philips panhead"
H5 H6 H7 H8: "Standoff, Hex, 0.5\"L #4-40 Nylon"
J1 J5: "Terminal Block, 2-pole, 200mil, TH"
J2: "Power Jack, mini, 2.1mm OD, R/A, TH"
J3: "Header, 100mil, 2x1, Tin, TH"
J4: "Header, 100mil, 3x1, Tin, TH"
J6: "Header, 100mil, 10x2, TH"
J7: "Header, 100mil, 3x2, Tin, TH"
J8: library part "09 66 252 6610", "D-Sub-15, 17Pos, TH"
J9: "Header, 100mil, 8x1, TH"
L1: "Inductor, Shielded Drum Core, Ferrite, 100 µH, 0.9 A, 0.33 ohm, SMD"
L2: "Inductor, Shielded Drum Core, Ferrite, 1 µH, 1.5 A, 0.09 ohm, SMD"
Logo1: library part TI_Logo, "Texas Instrument Corporate Signature"
R1: "RES, 10 ohm, 5%, 0.25W, 0603"
R2 R12: "RES, 1.0 k, 5%, 0.063 W, 0402"
R3: "RES, 681 k, 1%, 0.063 W, 0402"
R4: "RES, 10k ohm, 5%, 0.125W, 0805"
R5: "RES, 63.4 k, 1%, 0.063 W, 0402"
R6: "RES, 51 ohm, 5%, 0.1W, 0603"
R7: "RES, 64.9 k, 1%, 0.063 W, 0402"
R8: "RES, 237 k, 1%, 0.063 W, 0402"
R9: "RES, 46.4 k, 1%, 0.063 W, 0402"
R10: "RES, 10.0 k, 1%, 0.063 W, 0402"
R11: "RES, 340 k, 1%, 0.063 W, 0402"
R13: "RES, 100 k, 5%, 0.063 W, 0402"
R14 R17 R56: "RES, 0, 5%, 0.063 W, 0402"
R15: "RES, 845 k, 1%, 0.063 W, 0402"
R16: "RES, 160 k, 5%, 0.063 W, 0402"
R18 R27 R30 R37: "Resistor Networks, 1K ohm, 5K ohm, SMD"
R19 R21 R23 R25 R31 R33 R34 R36 R38 R40 R44 R48 R59 R63 R75 R79: "RES, 10.0, 1%, 0.063 W, 0402"
R20 R32 R39: "RES, 120, 1%, 0.4 W, 0805"
R22 R26: "RES, 22, 5%, 0.063 W, 0402"
R24 R35: "RES, 10, 5%, 0.063 W, 0402"
R28 R29: "RES, 0.22, 1%, 0.1 W, 0603"
R41 R57: "RES, 100, 5%, 0.063 W, 0402"
R42 R73: "RES, 1.0, 5%, 0.063 W, 0402"
R43 R55 R58 R70 R74 R88: "RES, 8.45 k, 0.1%, 0.063 W, 0402"
R45 R54 R60 R69 R76 R87: "RES, 220, 5%, 0.063 W, 0402"
R46 R52 R61 R67 R77 R85: "RES, 332, 1%, 0.063 W, 0402"
R47 R53 R62 R68 R78 R86: "RES, 4.75 k, 0.1%, 0.063 W, 0402"
R49 R64 R80: "RES, 20.0, 1%, 0.063 W, 0402"
R50 R65 R81: "RES, 26.7 k, 1%, 0.063 W, 0402"
R51 R66 R83: "RES, 549 k, 1%, 0.063 W, 0402"
R71 R72 R82 R84: "RES, 1.00 k, 1%, 0.063 W, 0402"
TP1 TP4: "Test Point, Miniature, Black, TH"
TP2 TP3: "Test Point, Miniature, Red, TH"
TP5 TP6: "Test Point, Miniature, White, TH"
U1: "0.5 A, 42 V Step Down DC/DC Converter with Eco-mode, DGQ0010D"
U2: "Single Output High PSRR LDO, 200 mA, Adjustable 1.2 to 6.5 V Output, 2.7 to 6.5 V Input, with Low IQ, 6-pin SON (DRV), -40 to 85 degC, Green (RoHS & no Sb/Br)"
U3: "Single Output LDO, 150 mA, Adjustable 0.9 to 6.2 V Output, 2.5 to 6.5 V Input, with High-Bandwidth PSRR, 5-pin SC70 (DCK), -40 to 125 degC, Green (RoHS & no Sb/Br)"
U4: "Single Output High PSRR LDO, 200 mA, Fixed 3.3 V Output, 2.7 to 6.5 V Input, with Low IQ, 6-pin SON (DRV), -40 to 85 degC, Green (RoHS & no Sb/Br)"
U5: "Dual, High-Speed, 16-, 14-, and 12-Bit, Simultaneous-Sampling, Analog-to-Digital Converters, PW0016A"
U6 U7: "Ultra Low Power, Rail-to-Rail Output, Fully-Differential Amplifier, DGK0008A"
U8 U10 U12 U13 U14: "50 MHz, Low-Noise Single-Supply Rail-to-Rail Operational Amplifier, 2.2 to 5.5 V, -40 to 125 degC, 8-pin SOIC (D0008A), Green (RoHS & no Sb/Br)"
U9 U15: "40-ns, microPOWER, Push-Pull Output Comparators, D0008A"
U11: "Low-Drift, Low-Power, Dual-Output, VREF and VREF / 2 Voltage References, DDC0005A"

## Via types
v1: diameter 35.43, hole 19.68, Top Layer to Bottom Layer, 169 vias
v2: diameter 19.68, hole 7.87, Top Layer to Bottom Layer, 9 vias

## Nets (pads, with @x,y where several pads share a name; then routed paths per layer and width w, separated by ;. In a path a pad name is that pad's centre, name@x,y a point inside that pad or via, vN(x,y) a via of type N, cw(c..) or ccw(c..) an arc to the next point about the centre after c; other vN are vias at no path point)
A: J6.12 R51.2 U9.1 | length 455.7
  Bottom Layer w20: J6.12@218.57,2072.1 312.61,2072.1 489.85,2249.33 R51.2@528.71,2249.33 ; U9.1@528.74,2173.78 R51.2@528.74,2245.96
A_M: C38.2 C41.1 J8.9 J9.2 R32.1 R34.1 | length 546.9
  Top Layer w20: 2618.43,2347.15 2703.33,2347.15 2745.37,2305.11 2781.96,2305.11 2817.16,2340.31 3126.13,2340.31 J8.9@3131.24,2345.43
A_M1: D11.1 D12.2 R30.1 R34.2 R45.1 | length 892.1
  Top Layer w20: R30.1@2012.04,2246.95 2050.24,2246.95 2162,2358.71 v1@2239.57,2358.71 ; v1@2252.25,2357.85 D11.1@2292.98,2357.85 ; D11.1@2297.13,2358.54 2366.48,2358.53 2426.31,2358.53 R34.2@2430.36,2358.53
  Bottom Layer w20: R45.1@2102.65,2688.25 2102.65,2656.37 2123.28,2635.73 2164.79,2635.73 2214.48,2586.04 2214.48,2527 2285.79,2455.68 2285.79,2397.81 v1@2247.8,2359.81
  other v1: 2242.42,2359.53
A_P: C35.2 C38.1 J8.1 J9.1 R31.1 R32.2 | length 444.6
  Top Layer w20: 2611.22,2458.63 2684.31,2458.63 2742.05,2400.89 3029.72,2400.89 J8.1@3031.24,2399.36
A_P1: D9.1 D10.2 R31.2 R37.1 R54.1 | length 717.5
  Top Layer w20: R37.1@1919.96,2476.98 2045.22,2476.98 2079.92,2442.29 v1@2241.08,2442.29 ; v1@2238.81,2442.34 D9.1@2293.84,2442.34 ; D9.1@2300.6,2431.43 R31.2@2422.77,2431.43
  Bottom Layer w20: R54.1@2136.07,2592.2 2161.55,2592.2 2186.6,2567.15 2186.6,2494.08 v1@2236.69,2443.99
  other v1: 2241.6,2442.29
B: J6.14 R66.2 U9.7 | length 455.5
  Bottom Layer w20: J6.14@224.23,1959.45 435.86,1959.45 486.98,1908.33 R66.2@583.8,1908.33 ; R66.2@578.74,1910.01 U9.7@578.74,1984.81
B_M: C28.2 C31.1 J8.11 J9.4 R20.1 R23.1 | length 624.7
  Top Layer w20: 2624.81,2105.57 2870.16,2105.57 3006.73,2242.14 3044.64,2242.14 3081.42,2205.36 3081.42,2179.5 J8.11@3131.24,2129.68
B_M1: D7.1 D8.2 R23.2 R27.1 R60.1 | length 688.9
  Top Layer w20: R27.1@1905.9,2012.39 2156.65,2012.39 v1@2239.28,2095.01 ; v1@2236.49,2095.01 v1@2239.28,2095.01 ; v1@2242.14,2106.59 2242.14,2097.88 v1@2239.28,2095.01 ; R23.2@2431.56,2095.01 v1@2239.28,2095.01
  Bottom Layer w20: R60.1@2146.67,2059.93 2202.49,2059.93 v1(2243.28,2100.72)
B_P: C26.2 C28.1 J8.3 J9.5 R19.1 R20.2 | length 491.2
  Top Layer w20: 2614.36,2004.06 2851.69,2004.06 J8.3@3031.24,2183.61
B_P1: D5.1 D6.2 R18.1 R19.2 R69.1 | length 782.7
  Top Layer w20: R18.1@1995.4,1782.72 2024.71,1782.72 v1@2241.57,1999.58 ; v1@2251.11,2012.25 R19.2@2431.31,2012.25
  Bottom Layer w20: R69.1@2168.3,2177.43 2219.74,2177.43 2280.53,2116.63 2280.53,2040.41 v1(2243.15,2003.03)
COS: C63.1 J6.20 R57.2 | length 277.4
  Top Layer w20: J6.20@209.35,1660.63 R57.2@486.72,1660.63
CSN: J6.4 U5.11 | length 993
  Top Layer w10: 1001.92,2159.98 U5.11@1075.43,2159.98
  Top Layer w20: J6.4@208.75,2464.92 696.98,2464.92 1001.92,2159.98
ENC_VCC: J4.2 J8.4 J9.6 R12.2 | length 1982.1
  Top Layer w20: R12.2@2609.28,1114.27 J4.2@2781.18,1114.27
  Supply plane w20: J9.6@2779.94,1905.18 2834.68,1905.18 3004.25,2074.74 3191.88,2074.74
  Supply plane w50: J4.2@2776.23,1111.34 3048.84,1111.34 3231.42,1293.93 3231.42,2035.2 3191.88,2074.74
GND: C2.2 C3.2 C4.2 C5.2 C6.2 C7.2 C8.2 C9.2 C10.2 C11.2 C12.2 C13.2 C14.2 C16.2 C17.2 C18.2 C19.2 C20.2 C21.2 C22.2 C23.1 C24.1 C25.1 C26.1 C27.1 C31.2 C32.2 C33.1 C34.1 C35.1 C36.1 C37.2 C41.2 C42.2 C43.2 C45.1 C47.1 C48.2 C49.1 C50.1 C51.2 C52.2 C53.2 C54.2 C55.2 C56.2 C57.2 C59.1 C60.1 C62.1 C63.2 C64.2 C65.2 C66.2 C67.2 C68.2 C69.2 C70.2 C73.1 C74.1 C75.1 C76.2 C77.2 C78.2 C79.2 C80.2 C81.2 C82.2 D2.2 D3.2 D4.2 D5.2 D7.2 D9.2 D11.2 D13.2 D15.2 J1.2 J2.2 J2.3 J5.2 J6.1 J6.3 J6.5 J6.7 J6.9 J6.11 J6.13 J6.15 J6.17 J6.19 J7.1 J7.3 J7.5 J8.2 J9.3 R5.1 R8.1 R10.1 R13.1 R16.1 R72.1 R84.1 TP1.1 TP4.1 U1.9 U1.11 U2.3 U2.7 U3.2 U4.3 U4.7 U5.4 U5.5 U5.15 U6.6 U7.6 U8.4 U9.4 U10.4 U11.2 U12.4 U13.4 U14.4 U15.4 | length 4955.6
  Top Layer w10: 519.85,1110.23 602.69,1110.23 ; 997.62,2011.79 1043.45,2057.62 U5.15@1075.43,2057.62 1156.66,2057.62 ; U3.2@1690.49,1334.83 1690.49,1297.33 C19.2@1716.6,1271.22 ; 1795.57,1736.94 U6.6@1795.57,1817.35 ; 1810.1,2205.78 U7.6@1810.1,2276.9 ; U1.11@2159.17,323.12 2273.12,323.12 v1@2284.66,334.66 ; v1(2284.78,334.54) 2294.19,343.95 C13.2@2322.36,343.95 ; C14.2@2371.11,343.95 C14.2@2373.21,346.05
  Top Layer w20: U11.2@519.85,1158.43 519.85,1110.23 519.85,1025.09 530.63,1014.32 530.63,1013.62 ; C13.2@2322.36,343.95 C14.2@2369.36,343.95
  Ground plane w20: J9.3@2779.94,2205.18 2866.28,2205.18 2949.56,2288.46 3204.5,2288.46
  Ground plane w50: 2877.2,1109.66 3046.32,1109.66 3230.58,1293.93 3230.58,2262.37 3204.5,2288.46
  Supply plane w10: J7.3@110.21,1140.24 J7.3@110.21,1154.33
  Bottom Layer w10: 1904.88,2644.14 1906,2645.25 ; v1@1905.87,1615.83 v1@1906.37,1616.33 ; 1912.01,2107.61 1912.64,2106.98 ; 1954.88,2837.62 1954.88,2645.64 1955.26,2645.25 ; 1955.87,1830.97 1955.87,1619.1 1958.64,1616.33 ; 1963.27,2313.23 1963.27,2112.01 v1@1967.67,2107.61 ; v1@2002.27,1616.33 2005.24,1613.36 2005.24,1367.53 ; 2002.27,2645.25 2004.25,2643.28 2004.25,2417.43 ; 2012.8,1884.98 v1@2012.8,2107.61
  Bottom Layer w20: C47.1@1796.17,2645.25 1906,2645.25 1955.26,2645.25 2002.27,2645.25 2020.28,2645.25 2029.36,2654.34 U8.4@2029.36,2708.85 ; C73.1@1798.1,1616.33 1906.37,1616.33 1958.64,1616.33 2002.27,1616.33 2013.16,1616.33 2031.33,1634.5 U14.4@2031.33,1694.8 ; C62.1@1806.08,2107.61 1912.01,2107.61 1967.67,2107.61 2012.8,2107.61 2026.47,2107.61 2037.53,2118.68 U12.4@2037.53,2159.47
  other v1: 2012.25,110.93 1910.95,111.86 1519.26,127.37 2238.68,134.2 375.19,183.81 421.96,183.81 468.74,183.81 3302.1,236.3 1079.3,252.75 357.93,261.36 357.93,311.99 3302.1,317.91 3233.95,322.12 1077.48,323.16 1009.34,324.07 357.93,362.04 2374.56,391.58 730.92,654.8 976.93,654.8 1137.2,712.57 1206.16,781.53 2385.88,794.58 1253.31,826.96 2658.15,935 548.02,944.01 2551.39,960.19 741.94,1016.23 2893.07,1049.45 1682.85,1087.43 986.67,1097.09 2462.07,1121.57 862.04,1138.29 617.69,1151.93 2892.34,1167.97 2276.37,1187.11 2396.05,1204.69 426.25,1260.97 1546.49,1319.27 1608.09,1319.27 1768.78,1319.28 1791.14,1378.07 2059.84,1377.56 1975.86,1422.21 2503.06,1436.22 1053.91,1458.23 779.91,1465.71 1007.43,1474.07 1160.29,1480.51 2618.25,1521.65 2561.54,1563.69 341.49,1570.61 2270.86,1570.56 2317.82,1572.96 1903.96,1605.78 2010.28,1608.08 1490.2,1610.47 732.24,1615.09 1646.43,1618.41 880.76,1640.73 1840.9,1656.3 1788.77,1690.11 509.61,1716.04 1686.47,1807.61 1170.18,1813.36 340.12,1817.36 624.09,1825.66 2293.21,1845.02 1552.11,1854.46 1655.03,1862.91 889.22,1864.49 2052.41,1870.55 2668.75,1884.88 2568.8,1888.97 1980,1896.01 2293.91,1914.16 764.16,1947.68 719.59,1949.16 2100.95,1962.27 454.48,2007.99 1716.82,2030.03 2016.6,2091.13 1950.76,2104.95 1203.48,2108.34 1154.8,2108.69 651.25,2112.18 1854.55,2119.76 1154.8,2147.65 1203.48,2147.65 2293.91,2185.09 1730.52,2194.59 1686.22,2204.8 837.24,2210.1 350.53,2215.5 2663.75,2224.23 2564.72,2228.32 1734.43,2239.1 2296.02,2259.84 417.76,2316.62 2071.32,2338.16 2017.52,2361.39 1677.06,2390.67 2079.15,2401.34 417.76,2413.33 1247.11,2435.15 1677.06,2499.08 417.76,2516.89 2261.25,2535.23 2318.6,2536.43 2566.78,2546.13 854.92,2575.94 2616.93,2586.95 1998.09,2611.28 1912.94,2613.13 1849.02,2660.95 1602.61,2747.43 1316.79,2801.24 2085.21,2815.89
  other v2: 2115.29,279.8 2150.73,279.8 2133.01,303.43 2115.29,327.05 2150.73,327.05 963.34,1244.89 963.34,1276.39 2451.65,1282.62 2451.65,1314.12
NetC1_1: C1.1 D2.1 L1.1 R4.2 U1.10 | length 451.2
  Top Layer w10: v1@1826.36,377.73 1838.09,365.99 1867.83,365.99 C1.1@1877.29,356.53
  Bottom Layer w10: v1@1830.74,382.85 2207.56,382.85 v1@2217.97,393.26
  other v1: 1818.29,379.58 2217.7,385.91
NetC1_2: C1.2 U1.1 | length 113.1
  Top Layer w10: C1.2@1950.86,342.8 U1.1@2063.99,342.8
NetC2_1: C2.1 C3.1 C4.1 J3.2 L1.2 R2.2 R6.1 TP3.1 | length 1811.4
  Top Layer w20: R6.1@2464.7,244.93 TP3.1@2464.7,465.7
  Top Layer w50: R2.2@1490.43,824.65 C4.1@1579.27,824.65
  Bottom Layer w20: J3.2@1548.75,981.13 1548.75,1003.74 1679.22,1134.2 2195.03,1134.2 2466.93,862.3 TP3.1@2466.93,467.93
NetC5_1: C5.1 C6.1 C7.1 D1.1 L2.1 R1.1 | length 283
  Top Layer w20: R1.1@1263.52,380.59 L2.1@1329.26,380.59
  Top Layer w50: 1428.2,417.63 C5.1@1428.2,634.86
NetC8_1: C8.1 C9.1 C10.1 L2.2 R1.2 R3.2 U1.2 | length 924.8
  Top Layer w10: 1879.61,323.12 U1.2@2063.99,323.12
  Top Layer w20: R1.2@1263.52,317.6 L2.2@1342.21,317.6 ; C10.1@1797.82,323.75 1797.82,323.08 1797.82,319.93 1943.9,319.93 ; R3.2@1860.03,252.61 1860.03,315.31
  Top Layer w50: 1348.66,323.08 C10.1@1797.82,323.08
NetC11_1: C11.1 R4.1 | length 71.8
  Top Layer w50: C11.1@2056.48,593.43 R4.1@2128.32,593.43
NetC12_1: C12.1 U1.4 | length 149.7
  Top Layer w10: C12.1@1961.7,216.43 1961.7,249.81 1995.64,283.75 U1.4@2063.99,283.75
NetC13_1: C13.1 R9.2 U1.8 | length 139.2
  Top Layer w10: U1.8@2225.4,303.43 C13.1@2317.28,303.43
  Top Layer w20: R9.2@2322.94,250.78 C13.1@2322.94,298.06
NetC14_1: C14.1 R9.1 | length 49.9
  Top Layer w20: R9.1@2372.94,248.12 C14.1@2372.94,298.06
NetC15_1: C15.1 C16.1 J4.1 R11.2 U2.1 | length 183.9
  Top Layer w10: U2.1@2490.04,1272.78 R11.2@2549.68,1272.78
  Top Layer w20: C16.1@2551.65,1208.37 R11.2@2551.65,1274.75 C15.1@2609.53,1274.75
NetC15_2: C15.2 R11.1 R13.2 U2.2 | length 71.4
  Top Layer w10: U2.2@2490.04,1298.37 2506.15,1298.37 2529.77,1321.99 R11.1@2551.65,1321.99
NetC18_1: C18.1 R14.1 R15.2 U3.5 | length 61.7
  Top Layer w20: C18.1@1559.29,1467.87 R14.1@1559.29,1529.56
NetC20_1: C20.1 R17.1 U4.1 | length 143.5
  Top Layer w20: R17.1@856.22,1375.78 C20.1@919.24,1375.78 ; U4.1@923.43,1290.42 C20.1@923.43,1370.87
NetC22_1: C22.1 U4.2 | length 59.9
  Top Layer w20: C22.1@865.07,1260.64 U4.2@924.95,1260.64
NetC29_1: C29.1 C30.1 R21.2 U5.1 | length 202.2
  Top Layer w10: U5.1@1299.84,2032.03 1342.05,2032.03 1348.76,2025.31 1348.76,2008.66 1360.63,1996.8 C30.1@1375.2,1996.8
  Top Layer w20: C30.1@1391.13,1980.9 R21.2@1493.63,1980.9
NetC29_2: C29.2 C30.2 R25.2 U5.2 | length 188
  Top Layer w10: U5.2@1299.84,2057.62 1341.73,2057.62 1354.89,2044.46 C30.2@1376.24,2044.46
  Top Layer w20: C30.2@1387.97,2035.25 R25.2@1494.17,2035.25
NetC32_1: C32.1 R24.2 U6.2 | length 311.5
  Top Layer w10: R24.2@1716.97,2098.98 C32.1@1716.97,2148.17 ; C32.1@1717.25,2148.88 1774.62,2148.88 1822.34,2101.16 U6.2@1822.34,1963.72
NetC36_2: C36.2 R28.1 | length 67.9
  Top Layer w20: C36.2@1230.92,1890.54 R28.1@1298.83,1890.54
NetC37_1: C37.1 R29.1 | length 58.6
  Top Layer w20: C37.1@1232.36,2338.73 R29.1@1290.92,2338.73
NetC39_1: C39.1 C40.1 R33.2 U5.7 | length 196.8
  Top Layer w10: U5.7@1299.84,2185.57 C40.1@1392.72,2185.57
  Top Layer w20: C40.1@1394.08,2177.07 R33.2@1498.04,2177.07
NetC39_2: C39.2 C40.2 R36.2 U5.8 | length 192.5
  Top Layer w10: U5.8@1299.93,2212.77 C40.2@1389.92,2212.77
  Top Layer w20: C40.2@1395.73,2229.96 R36.2@1498.23,2229.96
NetC42_1: C42.1 R35.2 U7.2 | length 194
  Top Layer w10: R35.2@1768.32,2569.36 C42.1@1831.77,2569.36 C42.1@1834.12,2569.36 ; U7.2@1835.7,2442.25 C42.1@1835.7,2570.42
NetC46_1: C46.1 R43.2 R48.1 U10.1 | length 222.8
  Bottom Layer w20: R48.1@1222.98,2571.96 C46.1@1325.57,2571.96 ; U10.1@1329.95,2499.42 C46.1@1329.95,2570.73 ; R43.2@1329.95,2617.99 C46.1@1329.95,2570.73 ; C46.1@1331.59,2570.73 C46.1@1329.95,2570.73
NetC46_2: C46.2 R43.1 R47.2 U10.2 | length 172.4
  Bottom Layer w20: R43.1@1378.51,2621.42 R47.2@1378.51,2673.25 ; U10.2@1379.95,2499.42 R43.1@1379.95,2619.96
NetC51_1: C51.1 R44.2 U9.2 | length 226.4
  Bottom Layer w20: R44.2@410.85,2109.05 C51.1@455.76,2109.05 ; C51.1@453.32,2110.67 566.79,2110.67 578.74,2122.62 U9.2@578.74,2173.78
NetC52_1: C52.1 R45.2 U8.3 | length 257.3
  Bottom Layer w20: C52.1@1979.09,2816.66 1979.09,2776.08 1979.56,2776.08 ; U8.3@1979.56,2714.6 1979.56,2776.08 ; R45.2@2102.65,2735.5 2102.65,2760.94 2087.5,2776.08 1979.56,2776.08
NetC53_1: C53.1 R46.2 R47.1 | length 306.5
  Bottom Layer w20: R47.1@1378.47,2721.67 1496.98,2721.67 1574.98,2643.67 ; 1577.23,2643.14 R46.2@1654.88,2643.14
NetC54_1: C54.1 R49.2 R50.1 | length 127.5
  Bottom Layer w20: R50.1@681.39,2249.81 683.11,2251.53 708.93,2251.53 725.52,2268.13 C54.1@744.75,2268.13 ; C54.1@749.85,2271.27 R49.2@749.85,2327.86
NetC55_1: C55.1 R52.2 R53.1 | length 198.9
  Bottom Layer w20: R53.1@1489.43,2669.84 1508.53,2669.84 1587.62,2591.22 R52.2@1655.9,2591.22
NetC56_1: C56.1 R54.2 U8.5 | length 186.6
  Bottom Layer w20: C56.1@2029.56,2457.29 U8.5@2029.56,2525.63 ; U8.5@2030.43,2528.28 2030.43,2585.3 2037.33,2592.2 R54.2@2088.83,2592.2
NetC58_2: C58.2 R53.2 R55.1 U10.3 | length 171.1
  Bottom Layer w20: U10.3@1429.95,2499.42 R53.2@1429.95,2670.56
NetC60_2: C60.2 R56.1 U11.1 | length 127.6
  Top Layer w20: U11.1@553.66,1157.21 R56.1@553.66,1284.82
NetC61_1: C61.1 R58.2 R63.1 U10.7 | length 711.7
  Bottom Layer w20: R63.1@1073.64,1913.55 1329.35,1913.55 1378.77,1962.97 C61.1@1378.77,2228.3 ; R58.2@1379.95,2178.69 U10.7@1379.95,2299.42
NetC61_2: C61.2 R58.1 R62.2 U10.6 | length 170.6
  Bottom Layer w20: R62.2@1429.95,2128.84 U10.6@1429.95,2299.42
NetC64_1: C64.1 R59.2 U9.6 | length 233
  Bottom Layer w20: U9.6@628.74,1984.81 628.74,2033.82 641.08,2046.16 711.66,2046.16 711.83,2046.33 C64.1@751.87,2046.33 ; C64.1@755.36,2046.09 R59.2@810.99,2046.09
